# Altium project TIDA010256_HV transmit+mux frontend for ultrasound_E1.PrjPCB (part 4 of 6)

## Sheet 17_AM243x_SocPower.SchDoc
size 431 x 279 mm; Date: Not shown in title block; ApprovedBy: Not shown in title block; CheckedBy: Not shown in title block; Author: Not shown in title block; CompanyName: Not shown in title block; Engineer: Not shown in title block; Organization: Not shown in title block; Address1: Not shown in title block; Address2: Not shown in title block; Address3: Not shown in title block; Address4: Not shown in title block; DocumentNumber: 9; Revision: Use project parameter SCH_Rev; SheetNumber: 9; SheetTotal: 18; PageSetup: Record=PageOptions¦CenterHorizontal=True¦CenterVertical=True¦PrintScale=1.00¦XCorrection=1.00¦YCorrection=1.00¦PrintKind=0¦BorderSize=5000000¦LeftOffset=0¦BottomOffset=0¦Orientation=2¦PaperLength=1000¦PaperWidth=1000¦Scale=100¦PaperSource=15¦PrintQuality=600¦MediaType=1¦DitherType=10¦PaperKind=Letter¦PrintScaleMode=1
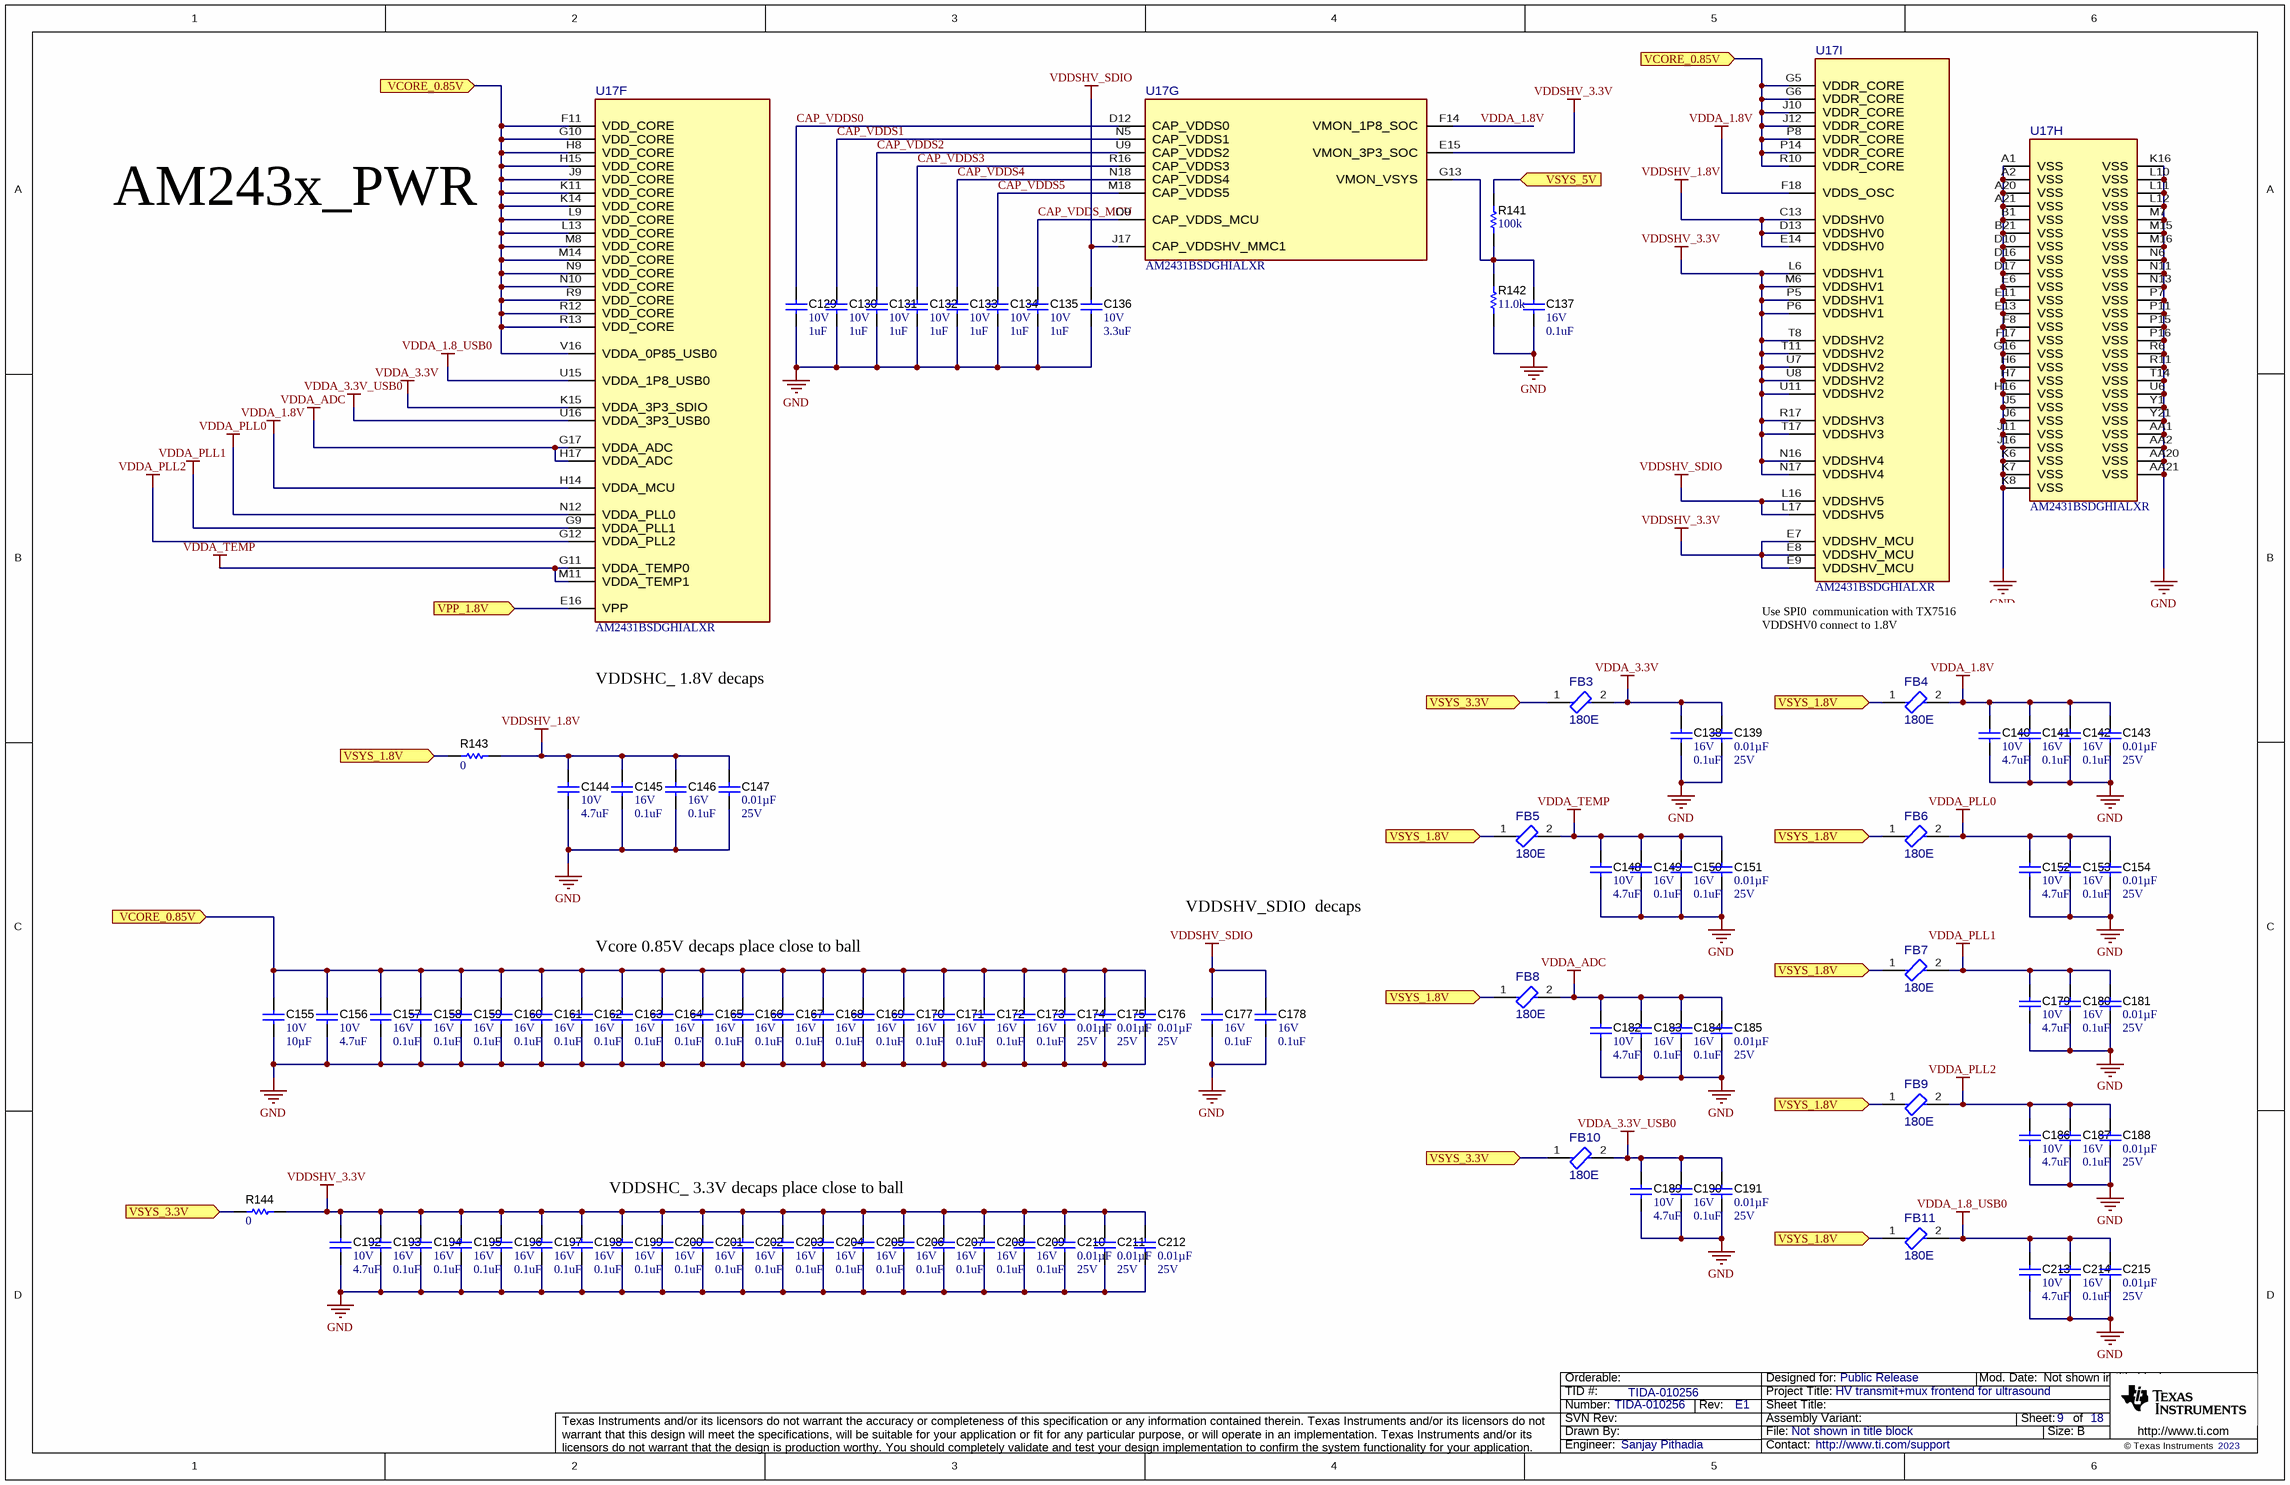
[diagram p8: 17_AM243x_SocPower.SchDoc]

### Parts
C129  VDC_V: 10V  ValueDisplayed: 1uF  [0402]  (hidden comment: GRM155R61A105KE15D)
C130  VDC_V: 10V  ValueDisplayed: 1uF  [0402]  (hidden comment: GRM155R61A105KE15D)
C131  VDC_V: 10V  ValueDisplayed: 1uF  [0402]  (hidden comment: GRM155R61A105KE15D)
C132  VDC_V: 10V  ValueDisplayed: 1uF  [0402]  (hidden comment: GRM155R61A105KE15D)
C133  VDC_V: 10V  ValueDisplayed: 1uF  [0402]  (hidden comment: GRM155R61A105KE15D)
C134  VDC_V: 10V  ValueDisplayed: 1uF  [0402]  (hidden comment: GRM155R61A105KE15D)
C135  VDC_V: 10V  ValueDisplayed: 1uF  [0402]  (hidden comment: GRM155R61A105KE15D)
C136  VDC_V: 10V  ValueDisplayed: 3.3uF  [0603]  (hidden comment: C1608X7S1A335K080AC)
C137  VDC_V: 16V  ValueDisplayed: 0.1uF  [0201_033]  (hidden comment: GRM033R61C104KE84D)
C138  VDC_V: 16V  ValueDisplayed: 0.1uF  [0201_033]  (hidden comment: GRM033R61C104KE84D)
C139  ValueDisplayed: 0.01µF  VDC_V: 25V  [0201]  (hidden comment: GRM033R71E103KE14D)
C140  VDC_V: 10V  ValueDisplayed: 4.7uF  [0402]  (hidden comment: GRM155R61A475MEAAD)
C141  VDC_V: 16V  ValueDisplayed: 0.1uF  [0201_033]  (hidden comment: GRM033R61C104KE84D)
C142  VDC_V: 16V  ValueDisplayed: 0.1uF  [0201_033]  (hidden comment: GRM033R61C104KE84D)
C143  ValueDisplayed: 0.01µF  VDC_V: 25V  [0201]  (hidden comment: GRM033R71E103KE14D)
C144  VDC_V: 10V  ValueDisplayed: 4.7uF  [0402]  (hidden comment: GRM155R61A475MEAAD)
C145  VDC_V: 16V  ValueDisplayed: 0.1uF  [0201_033]  (hidden comment: GRM033R61C104KE84D)
C146  VDC_V: 16V  ValueDisplayed: 0.1uF  [0201_033]  (hidden comment: GRM033R61C104KE84D)
C147  ValueDisplayed: 0.01µF  VDC_V: 25V  [0201]  (hidden comment: GRM033R71E103KE14D)
C148  VDC_V: 10V  ValueDisplayed: 4.7uF  [0402]  (hidden comment: GRM155R61A475MEAAD)
C149  VDC_V: 16V  ValueDisplayed: 0.1uF  [0201_033]  (hidden comment: GRM033R61C104KE84D)
C150  VDC_V: 16V  ValueDisplayed: 0.1uF  [0201_033]  (hidden comment: GRM033R61C104KE84D)
C151  ValueDisplayed: 0.01µF  VDC_V: 25V  [0201]  (hidden comment: GRM033R71E103KE14D)
C152  VDC_V: 10V  ValueDisplayed: 4.7uF  [0402]  (hidden comment: GRM155R61A475MEAAD)
C153  VDC_V: 16V  ValueDisplayed: 0.1uF  [0201_033]  (hidden comment: GRM033R61C104KE84D)
C154  ValueDisplayed: 0.01µF  VDC_V: 25V  [0201]  (hidden comment: GRM033R71E103KE14D)
C155  VDC_V: 10V  ValueDisplayed: 10µF  [0402_070]  (hidden comment: GRM155R61A106ME44)
C156  VDC_V: 10V  ValueDisplayed: 4.7uF  [0402]  (hidden comment: GRM155R61A475MEAAD)
C157  VDC_V: 16V  ValueDisplayed: 0.1uF  [0201_033]  (hidden comment: GRM033R61C104KE84D)
C158  VDC_V: 16V  ValueDisplayed: 0.1uF  [0201_033]  (hidden comment: GRM033R61C104KE84D)
C159  VDC_V: 16V  ValueDisplayed: 0.1uF  [0201_033]  (hidden comment: GRM033R61C104KE84D)
C160  VDC_V: 16V  ValueDisplayed: 0.1uF  [0201_033]  (hidden comment: GRM033R61C104KE84D)
C161  VDC_V: 16V  ValueDisplayed: 0.1uF  [0201_033]  (hidden comment: GRM033R61C104KE84D)
C162  VDC_V: 16V  ValueDisplayed: 0.1uF  [0201_033]  (hidden comment: GRM033R61C104KE84D)
C163  VDC_V: 16V  ValueDisplayed: 0.1uF  [0201_033]  (hidden comment: GRM033R61C104KE84D)
C164  VDC_V: 16V  ValueDisplayed: 0.1uF  [0201_033]  (hidden comment: GRM033R61C104KE84D)
C165  VDC_V: 16V  ValueDisplayed: 0.1uF  [0201_033]  (hidden comment: GRM033R61C104KE84D)
C166  VDC_V: 16V  ValueDisplayed: 0.1uF  [0201_033]  (hidden comment: GRM033R61C104KE84D)
C167  VDC_V: 16V  ValueDisplayed: 0.1uF  [0201_033]  (hidden comment: GRM033R61C104KE84D)
C168  VDC_V: 16V  ValueDisplayed: 0.1uF  [0201_033]  (hidden comment: GRM033R61C104KE84D)
C169  VDC_V: 16V  ValueDisplayed: 0.1uF  [0201_033]  (hidden comment: GRM033R61C104KE84D)
C170  VDC_V: 16V  ValueDisplayed: 0.1uF  [0201_033]  (hidden comment: GRM033R61C104KE84D)
C171  VDC_V: 16V  ValueDisplayed: 0.1uF  [0201_033]  (hidden comment: GRM033R61C104KE84D)
C172  VDC_V: 16V  ValueDisplayed: 0.1uF  [0201_033]  (hidden comment: GRM033R61C104KE84D)
C173  VDC_V: 16V  ValueDisplayed: 0.1uF  [0201_033]  (hidden comment: GRM033R61C104KE84D)
C174  ValueDisplayed: 0.01µF  VDC_V: 25V  [0201]  (hidden comment: GRM033R71E103KE14D)
C175  ValueDisplayed: 0.01µF  VDC_V: 25V  [0201]  (hidden comment: GRM033R71E103KE14D)
C176  ValueDisplayed: 0.01µF  VDC_V: 25V  [0201]  (hidden comment: GRM033R71E103KE14D)
C177  VDC_V: 16V  ValueDisplayed: 0.1uF  [0201_033]  (hidden comment: GRM033R61C104KE84D)
C178  VDC_V: 16V  ValueDisplayed: 0.1uF  [0201_033]  (hidden comment: GRM033R61C104KE84D)
C179  VDC_V: 10V  ValueDisplayed: 4.7uF  [0402]  (hidden comment: GRM155R61A475MEAAD)
C180  VDC_V: 16V  ValueDisplayed: 0.1uF  [0201_033]  (hidden comment: GRM033R61C104KE84D)
C181  ValueDisplayed: 0.01µF  VDC_V: 25V  [0201]  (hidden comment: GRM033R71E103KE14D)
C182  VDC_V: 10V  ValueDisplayed: 4.7uF  [0402]  (hidden comment: GRM155R61A475MEAAD)
C183  VDC_V: 16V  ValueDisplayed: 0.1uF  [0201_033]  (hidden comment: GRM033R61C104KE84D)
C184  VDC_V: 16V  ValueDisplayed: 0.1uF  [0201_033]  (hidden comment: GRM033R61C104KE84D)
C185  ValueDisplayed: 0.01µF  VDC_V: 25V  [0201]  (hidden comment: GRM033R71E103KE14D)
C186  VDC_V: 10V  ValueDisplayed: 4.7uF  [0402]  (hidden comment: GRM155R61A475MEAAD)
C187  VDC_V: 16V  ValueDisplayed: 0.1uF  [0201_033]  (hidden comment: GRM033R61C104KE84D)
C188  ValueDisplayed: 0.01µF  VDC_V: 25V  [0201]  (hidden comment: GRM033R71E103KE14D)
C189  VDC_V: 10V  ValueDisplayed: 4.7uF  [0402]  (hidden comment: GRM155R61A475MEAAD)
C190  VDC_V: 16V  ValueDisplayed: 0.1uF  [0201_033]  (hidden comment: GRM033R61C104KE84D)
C191  ValueDisplayed: 0.01µF  VDC_V: 25V  [0201]  (hidden comment: GRM033R71E103KE14D)
C192  VDC_V: 10V  ValueDisplayed: 4.7uF  [0402]  (hidden comment: GRM155R61A475MEAAD)
C193  VDC_V: 16V  ValueDisplayed: 0.1uF  [0201_033]  (hidden comment: GRM033R61C104KE84D)
C194  VDC_V: 16V  ValueDisplayed: 0.1uF  [0201_033]  (hidden comment: GRM033R61C104KE84D)
C195  VDC_V: 16V  ValueDisplayed: 0.1uF  [0201_033]  (hidden comment: GRM033R61C104KE84D)
C196  VDC_V: 16V  ValueDisplayed: 0.1uF  [0201_033]  (hidden comment: GRM033R61C104KE84D)
C197  VDC_V: 16V  ValueDisplayed: 0.1uF  [0201_033]  (hidden comment: GRM033R61C104KE84D)
C198  VDC_V: 16V  ValueDisplayed: 0.1uF  [0201_033]  (hidden comment: GRM033R61C104KE84D)
C199  VDC_V: 16V  ValueDisplayed: 0.1uF  [0201_033]  (hidden comment: GRM033R61C104KE84D)
C200  VDC_V: 16V  ValueDisplayed: 0.1uF  [0201_033]  (hidden comment: GRM033R61C104KE84D)
C201  VDC_V: 16V  ValueDisplayed: 0.1uF  [0201_033]  (hidden comment: GRM033R61C104KE84D)
C202  VDC_V: 16V  ValueDisplayed: 0.1uF  [0201_033]  (hidden comment: GRM033R61C104KE84D)
C203  VDC_V: 16V  ValueDisplayed: 0.1uF  [0201_033]  (hidden comment: GRM033R61C104KE84D)
C204  VDC_V: 16V  ValueDisplayed: 0.1uF  [0201_033]  (hidden comment: GRM033R61C104KE84D)
C205  VDC_V: 16V  ValueDisplayed: 0.1uF  [0201_033]  (hidden comment: GRM033R61C104KE84D)
C206  VDC_V: 16V  ValueDisplayed: 0.1uF  [0201_033]  (hidden comment: GRM033R61C104KE84D)
C207  VDC_V: 16V  ValueDisplayed: 0.1uF  [0201_033]  (hidden comment: GRM033R61C104KE84D)
C208  VDC_V: 16V  ValueDisplayed: 0.1uF  [0201_033]  (hidden comment: GRM033R61C104KE84D)
C209  VDC_V: 16V  ValueDisplayed: 0.1uF  [0201_033]  (hidden comment: GRM033R61C104KE84D)
C210  ValueDisplayed: 0.01µF  VDC_V: 25V  [0201]  (hidden comment: GRM033R71E103KE14D)
C211  ValueDisplayed: 0.01µF  VDC_V: 25V  [0201]  (hidden comment: GRM033R71E103KE14D)
C212  ValueDisplayed: 0.01µF  VDC_V: 25V  [0201]  (hidden comment: GRM033R71E103KE14D)
C213  VDC_V: 10V  ValueDisplayed: 4.7uF  [0402]  (hidden comment: GRM155R61A475MEAAD)
C214  VDC_V: 16V  ValueDisplayed: 0.1uF  [0201_033]  (hidden comment: GRM033R61C104KE84D)
C215  ValueDisplayed: 0.01µF  VDC_V: 25V  [0201]  (hidden comment: GRM033R71E103KE14D)
FB3  180E  [FP-MPZ1608S181ATAH0_0603-MFG]
FB4  180E  [FP-MPZ1608S181ATAH0_0603-MFG]
FB5  180E  [FP-MPZ1608S181ATAH0_0603-MFG]
FB6  180E  [FP-MPZ1608S181ATAH0_0603-MFG]
FB7  180E  [FP-MPZ1608S181ATAH0_0603-MFG]
FB8  180E  [FP-MPZ1608S181ATAH0_0603-MFG]
FB9  180E  [FP-MPZ1608S181ATAH0_0603-MFG]
FB10  180E  [FP-MPZ1608S181ATAH0_0603-MFG]
FB11  180E  [FP-MPZ1608S181ATAH0_0603-MFG]
R141  ValueDisplayed: 100k  [0402]  (hidden comment: RC0402FR-07100KL)
R142  ValueDisplayed: 11.0k  [0402]  (hidden comment: CRCW040211K0FKED)
R143  ValueDisplayed: 0  [0402]  (hidden comment: RK73Z1ETTP)
R144  ValueDisplayed: 0  [0402]  (hidden comment: RK73Z1ETTP)
U17  AM2431BSDGHIALXR  [ALX0293A-MFG]  (parts F,G,H,I of 9)

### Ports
VCORE_0.85V (in), VPP_1.8V (in), VSYS_1.8V (in), VSYS_3.3V (in), VSYS_5V (in)

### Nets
GND: C129.2 C130.2 C131.2 C132.2 C133.2 C134.2 C135.2 C136.1 C137.2 C138.2 C139.2 C140.2 C141.2 C142.2 C143.2 C144.2 C145.2 C146.2 C147.2 C148.2 C149.2 C150.2 C151.2 C152.2 C153.2 C154.2 C155.2 C156.2 C157.2 C158.2 C159.2 C160.2 C161.2 C162.2 C163.2 C164.2 C165.2 C166.2 C167.2 C168.2 C169.2 C170.2 C171.2 C172.2 C173.2 C174.2 C175.2 C176.2 C177.2 C178.2 C179.2 C180.2 C181.2 C182.2 C183.2 C184.2 C185.2 C186.2 C187.2 C188.2 C189.2 C190.2 C191.2 C192.2 C193.2 C194.2 C195.2 C196.2 C197.2 C198.2 C199.2 C200.2 C201.2 C202.2 C203.2 C204.2 C205.2 C206.2 C207.2 C208.2 C209.2 C210.2 C211.2 C212.2 C213.2 C214.2 C215.2 R142.1 U17.A1(VSS) U17.A2(VSS) U17.A20(VSS) U17.A21(VSS) U17.AA1(VSS) U17.AA2(VSS) U17.AA20(VSS) U17.AA21(VSS) U17.B1(VSS) U17.B21(VSS) U17.D10(VSS) U17.D16(VSS) U17.D17(VSS) U17.E6(VSS) U17.E11(VSS) U17.E13(VSS) U17.F8(VSS) U17.F17(VSS) U17.G16(VSS) U17.H6(VSS) U17.H7(VSS) U17.H16(VSS) U17.J5(VSS) U17.J6(VSS) U17.J11(VSS) U17.J16(VSS) U17.K6(VSS) U17.K7(VSS) U17.K8(VSS) U17.K16(VSS) U17.L10(VSS) U17.L11(VSS) U17.L12(VSS) U17.M7(VSS) U17.M15(VSS) U17.M16(VSS) U17.N6(VSS) U17.N11(VSS) U17.N13(VSS) U17.P7(VSS) U17.P11(VSS) U17.P15(VSS) U17.P16(VSS) U17.R6(VSS) U17.R11(VSS) U17.T14(VSS) U17.U6(VSS) U17.Y1(VSS) U17.Y21(VSS)
VDDA_1.8_USB0: C213.1 C214.1 C215.1 FB11.2 U17.U15(VDDA_1P8_USB0)
VDDA_1.8V: C140.1 C141.1 C142.1 C143.1 FB4.2 U17.F14(VMON_1P8_SOC) U17.F18(VDDS_OSC) U17.H14(VDDA_MCU)
VDDA_3.3V: C138.1 C139.1 FB3.2 U17.K15(VDDA_3P3_SDIO)
VDDA_3.3V_USB0: C189.1 C190.1 C191.1 FB10.2 U17.U16(VDDA_3P3_USB0)
VDDA_ADC: C182.1 C183.1 C184.1 C185.1 FB8.2 U17.G17(VDDA_ADC) U17.H17(VDDA_ADC)
VDDA_PLL0: C152.1 C153.1 C154.1 FB6.2 U17.N12(VDDA_PLL0)
VDDA_PLL1: C179.1 C180.1 C181.1 FB7.2 U17.G9(VDDA_PLL1)
VDDA_PLL2: C186.1 C187.1 C188.1 FB9.2 U17.G12(VDDA_PLL2)
VDDA_TEMP: C148.1 C149.1 C150.1 C151.1 FB5.2 U17.G11(VDDA_TEMP0) U17.M11(VDDA_TEMP1)
VDDSHV_1.8V: C144.1 C145.1 C146.1 C147.1 R143.2 U17.C13(VDDSHV0) U17.D13(VDDSHV0) U17.E14(VDDSHV0)
VDDSHV_3.3V: C192.1 C193.1 C194.1 C195.1 C196.1 C197.1 C198.1 C199.1 C200.1 C201.1 C202.1 C203.1 C204.1 C205.1 C206.1 C207.1 C208.1 C209.1 C210.1 C211.1 C212.1 R144.2 U17.E7(VDDSHV_MCU) U17.E8(VDDSHV_MCU) U17.E9(VDDSHV_MCU) U17.E15(VMON_3P3_SOC) U17.L6(VDDSHV1) U17.M6(VDDSHV1) U17.N16(VDDSHV4) U17.N17(VDDSHV4) U17.P5(VDDSHV1) U17.P6(VDDSHV1) U17.R17(VDDSHV3) U17.T8(VDDSHV2) U17.T11(VDDSHV2) U17.T17(VDDSHV3) U17.U7(VDDSHV2) U17.U8(VDDSHV2) U17.U11(VDDSHV2)
VDDSHV_SDIO: C136.2 C177.1 C178.1 U17.J17(CAP_VDDSHV_MMC1) U17.L16(VDDSHV5) U17.L17(VDDSHV5)
CAP_VDDS0: C129.1 U17.D12(CAP_VDDS0)
CAP_VDDS1: C130.1 U17.N5(CAP_VDDS1)
CAP_VDDS2: C131.1 U17.U9(CAP_VDDS2)
CAP_VDDS3: C132.1 U17.R16(CAP_VDDS3)
CAP_VDDS4: C133.1 U17.N18(CAP_VDDS4)
CAP_VDDS5: C134.1 U17.M18(CAP_VDDS5)
CAP_VDDS_MCU: C135.1 U17.D9(CAP_VDDS_MCU)
VCORE_0.85V: C155.1 C156.1 C157.1 C158.1 C159.1 C160.1 C161.1 C162.1 C163.1 C164.1 C165.1 C166.1 C167.1 C168.1 C169.1 C170.1 C171.1 C172.1 C173.1 C174.1 C175.1 C176.1 U17.F11(VDD_CORE) U17.G5(VDDR_CORE) U17.G6(VDDR_CORE) U17.G10(VDD_CORE) U17.H8(VDD_CORE) U17.H15(VDD_CORE) U17.J9(VDD_CORE) U17.J10(VDDR_CORE) U17.J12(VDDR_CORE) U17.K11(VDD_CORE) U17.K14(VDD_CORE) U17.L9(VDD_CORE) U17.L13(VDD_CORE) U17.M8(VDD_CORE) U17.M14(VDD_CORE) U17.N9(VDD_CORE) U17.N10(VDD_CORE) U17.P8(VDDR_CORE) U17.P14(VDDR_CORE) U17.R9(VDD_CORE) U17.R10(VDDR_CORE) U17.R12(VDD_CORE) U17.R13(VDD_CORE) U17.V16(VDDA_0P85_USB0) ; port VCORE_0.85V
VSYS_1.8V: FB4.1 FB5.1 FB6.1 FB7.1 FB8.1 FB9.1 FB11.1 R143.1 ; port VSYS_1.8V
VSYS_3.3V: FB3.1 FB10.1 R144.1 ; port VSYS_3.3V
VSYS_5V: R141.2 ; port VSYS_5V
NetC96_1: U17.E16(VPP) ; port VPP_1.8V
NetC137_1: C137.1 R141.1 R142.2 U17.G13(VMON_VSYS)

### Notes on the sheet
- AM243x_PWR
- (near U17) Use SPI0  communication with TX7516
  VDDSHV0 connect to 1.8V
- VDDSHC_ 1.8V decaps
- Vcore 0.85V decaps place close to ball
- VDDSHV_SDIO  decaps
- VDDSHC_ 3.3V decaps place close to ball

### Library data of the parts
C129-C135 = CMP-0006563-2: CAP, CERM, 1 uF, 10 V, +/- 10%, X5R, 0402; Manufacturer: MuRata; TaMin_C: -55°C; Polarized: N; SizeAreaWB_mm2: 3; Value1: Unknown; U/M: EA; Value: 1uF; TaMax_C: 85°C; SizeZ_mm: 0.6; SizeX_mm: 1; SizeY_mm: 0.5; Cap_F: 1µF; AEC Category: Q200
C136 = CMP-0007057-4: CAP, CERM, 3.3 uF, 10 V, +/- 10%, X7S, 0603; Manufacturer: TDK; TaMin_C: -55°C; ESR_ohm: 4.796m; Polarized: N; SizeAreaWB_mm2: 4.68; Value1: 0.004796 ohm; U/M: EA; Value: 3.3uF; TaMax_C: 125°C; SizeZ_mm: 1; SizeX_mm: 1.6; SizeY_mm: 0.8; SizeArea_mm2: 1.28; Cap_F: 3.3µF; IRMS_A: 2.37519A; AEC Category: Q200
C137 C138 C141 C142 C145 C146 C149 C150 C153 C157-C173 C177 C178 C180 C183 C184 C187 C190 C193-C209 C214 = CMP-0009717-2: CAP, CERM, 0.1 uF, 16 V, +/- 10%, X5R, 0201; Manufacturer: MuRata; TaMin_C: -55°C; Polarized: N; SizeAreaWB_mm2: 2.08; Value1: Unknown; U/M: EA; Value: 0.1uF; TaMax_C: 85°C; SizeZ_mm: 0.33; SizeX_mm: 0.6; SizeY_mm: 0.3; Cap_Case: 0201; SizeArea_mm2: 0.18; Cap_F: 100nF; AEC Category: Q200
C139 C143 C147 C151 C154 C174-C176 C181 C185 C188 C191 C210-C212 C215 = CMP-0860568-1: CAP, CERM, 0.01 µF, 25 V,+/- 10%, X7R, 0201; Manufacturer: MuRata; U/M: EA; TaMax_C: 125°C; SizeZ_mm: 0.26; AEC Qualified: N; TaMin_C: -55°C; SizeY_mm: 0.3; AEC Category: Q200; SizeAreaWB_mm2: 2.08; Cap_F: 10nF; SizeX_mm: 0.6; Value: 0.01uF; SizeArea_mm2: 0.18
C140 C144 C148 C152 C156 C179 C182 C186 C189 C192 C213 = CMP-0006582-2: CAP, CERM, 4.7 uF, 10 V, +/- 20%, X5R, 0402; Manufacturer: MuRata; TaMin_C: -55°C; Polarized: N; SizeAreaWB_mm2: 3; Value1: Unknown; U/M: EA; Value: 4.7uF; TaMax_C: 85°C; SizeZ_mm: 0.6; SizeX_mm: 1; SizeY_mm: 0.5; Cap_F: 4.7µF; AEC Category: Q200
C155 = CMP-0074692-1: CAP, CERM, 10 µF, 10 V,+/- 20%, X5R, 0402; Manufacturer: MuRata; TaMin_C: -55°C; Polarized: N; Green_Lifecycle: Not Set; SizeAreaWB_mm2: 3.0; Green_REACh: Incomplete; U/M: EA; Value: 10uF; TaMax_C: 85°C; SizeZ_mm: 0.7; SizeX_mm: 1.0; SizeY_mm: 0.5; Cap_Case: 0402; AEC Category: Q200
FB3-FB11 = CMP-0092257-1: 180 Ohms @ 100MHz 1 Power Line Ferrite Bead 0603 (1608 Metric) 2A 50mOhm; PartNumber: MPZ1608S181ATAH0; Manufacturer: TDK Corporation; SizeZ_mm: 0.75mm; Tolerance_%: 25%; AEC Qualified: No; Impedance At Frequency: 180Ω @ 100MHz; DCR_ohm: 50m
R141 = CMP-0026721-1: RES, 100 k, 1%, 0.0625 W, 0402; Manufacturer: Yageo America; Power_W: 62.5mW; TempCo: 100 ppm/C; U/M: EA; Value: 100k; EIA_Code: E96; SizeX_mm: 1; SizeY_mm: 0.5; SizeZ_mm: 0.6; AEC Qualified: N; VDC_V: 50V; AEC Category: Q200
R142 = CMP-0025975-3: RES, 11.0 k, 1%, 0.063 W, AEC-Q200 Grade 0, 0402; Manufacturer: Vishay-Dale; Power_W: 63mW; TempCo: 100 ppm/C; Value_Code: 11k0; Value: 11.0k; EIA_Code: E96; Res_ohm: 11k; SizeX_mm: 1; SizeY_mm: 0.5; SizeZ_mm: 0.6; Value2: 0.063W; AEC Qualified: Y; VDC_V: 50V; AEC Category: Q200; AEC Grade: 0
R143 R144 = CMP-0027007-2: RES, 0, 5%, 0.063 W, AEC-Q200 Grade 0, 0402; Manufacturer: KOA Speer; Power_W: 63mW; TempCo: ppm/C; Value_Code: 0000; U/M: EA; Value: 0; EIA_Code: E24; SizeX_mm: 1; SizeY_mm: 0.5; SizeZ_mm: 0.6; Value2: 0.063W; AEC Qualified: Y; AEC Category: Q200
U17 = CMP-0035022-1: Arm® Cortex®-R5F-based MCU with industrial communications and security up to 800 MHz 293-FCCSP -40 to 125; Manufacturer: Texas Instruments; Number Of Pwm Channels: 7; Number Of Usb Channels: 1; Number Of Cores: 2; Standoff Height: 0.15mm; Ram Size: 2MBytes; Number Of I2C Channels: 3; Number Of Spi Channels: 4; SizeZ_mm: 1mm; Frequency_Fixed: 800MHz; Number Of I/Os: 148; AEC Qualified: No; Data Bus Width: 32bits; Core Architecture: Arm Cortex-R5F, Arm Cortex-M4F; TJmax_C: +125°C; Number Of Timers/Counters: 16; Max Supply Voltage: 3.465V; Min Supply Voltage: 810mV; Interface: I2C,SPI,UART,CAN,USB,Ethernet,PCIe,Other; Number Of Adc Channels: 8; Memory Type: OTHER

## Sheet 18_AM243x_Pinout.SchDoc
size 431 x 279 mm; Date: Not shown in title block; ApprovedBy: Not shown in title block; CheckedBy: Not shown in title block; Author: Not shown in title block; CompanyName: Not shown in title block; Engineer: Not shown in title block; Organization: Not shown in title block; Address1: Not shown in title block; Address2: Not shown in title block; Address3: Not shown in title block; Address4: Not shown in title block; DocumentNumber: 10; Revision: Use project parameter SCH_Rev; SheetNumber: 10; SheetTotal: 18; PageSetup: Record=PageOptions¦CenterHorizontal=True¦CenterVertical=True¦PrintScale=1.00¦XCorrection=1.00¦YCorrection=1.00¦PrintKind=0¦BorderSize=5000000¦LeftOffset=0¦BottomOffset=0¦Orientation=2¦PaperLength=1000¦PaperWidth=1000¦Scale=100¦PaperSource=15¦PrintQuality=600¦MediaType=1¦DitherType=10¦PaperKind=Letter¦PrintScaleMode=1
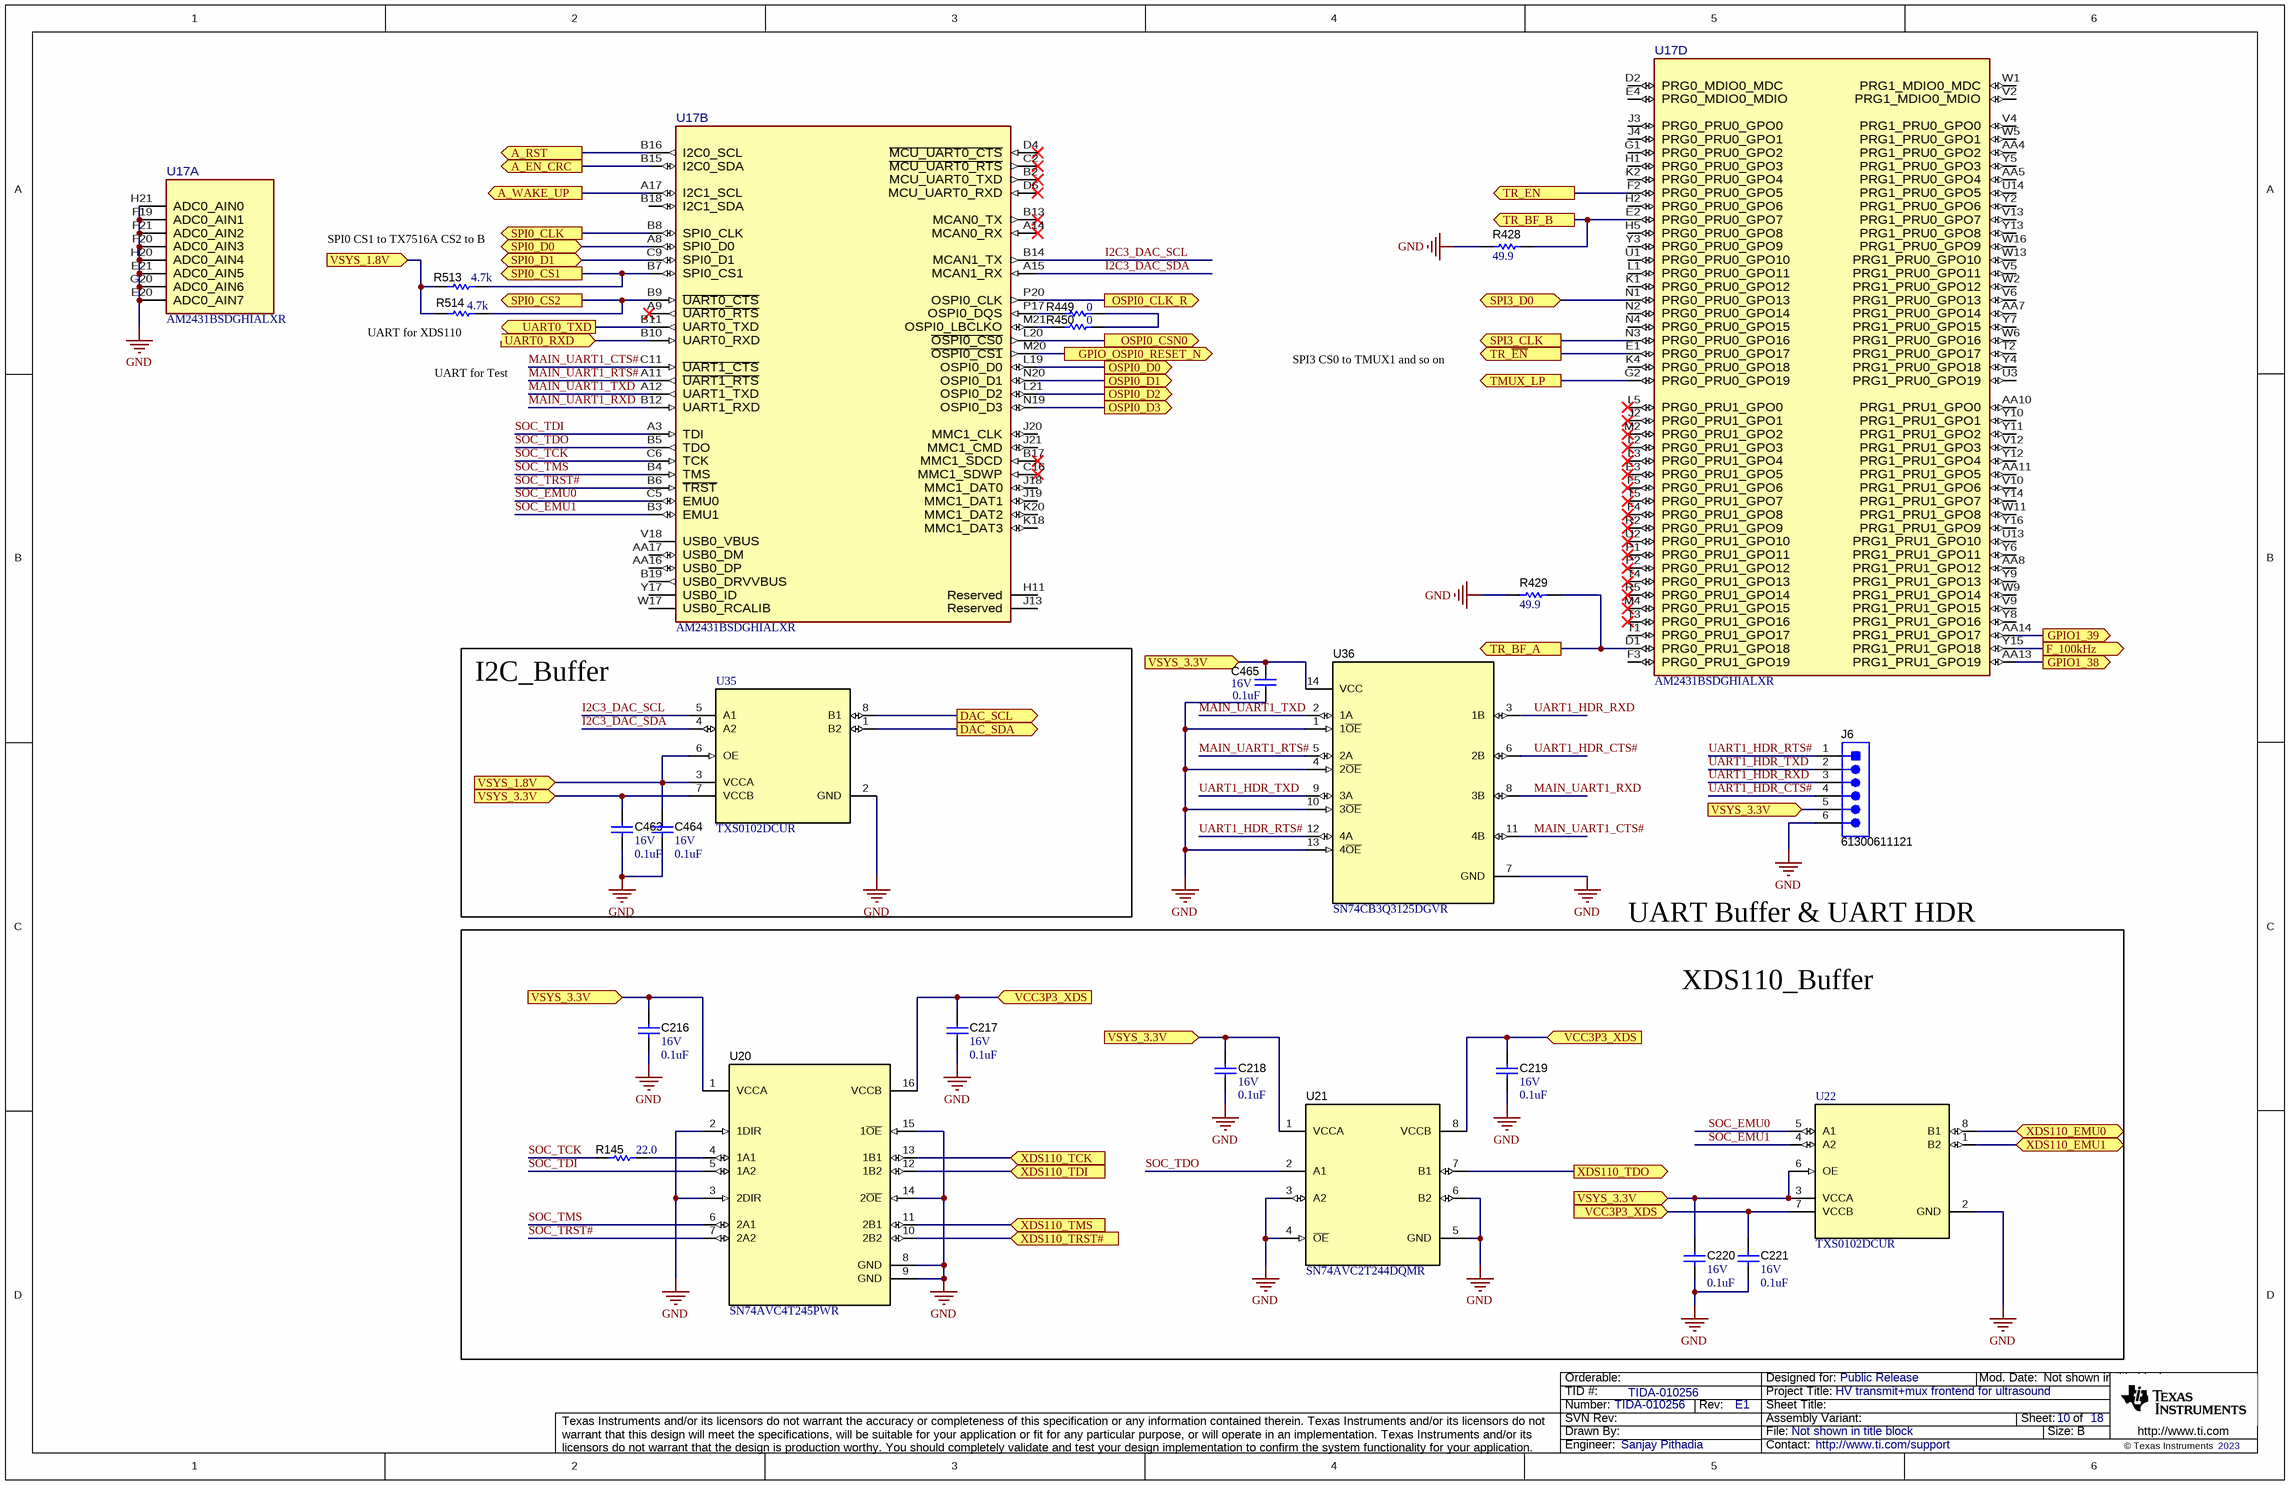
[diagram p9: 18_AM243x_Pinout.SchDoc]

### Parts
C216  VDC_V: 16V  ValueDisplayed: 0.1uF  [0201_033]  (hidden comment: GRM033R61C104KE84D)
C217  VDC_V: 16V  ValueDisplayed: 0.1uF  [0201_033]  (hidden comment: GRM033R61C104KE84D)
C218  VDC_V: 16V  ValueDisplayed: 0.1uF  [0201_033]  (hidden comment: GRM033R61C104KE84D)
C219  VDC_V: 16V  ValueDisplayed: 0.1uF  [0201_033]  (hidden comment: GRM033R61C104KE84D)
C220  VDC_V: 16V  ValueDisplayed: 0.1uF  [0201_033]  (hidden comment: GRM033R61C104KE84D)
C221  VDC_V: 16V  ValueDisplayed: 0.1uF  [0201_033]  (hidden comment: GRM033R61C104KE84D)
C463  VDC_V: 16V  ValueDisplayed: 0.1uF  [0201_033]  (hidden comment: GRM033R61C104KE84D)
C464  VDC_V: 16V  ValueDisplayed: 0.1uF  [0201_033]  (hidden comment: GRM033R61C104KE84D)
C465  VDC_V: 16V  ValueDisplayed: 0.1uF  [0201_033]  (hidden comment: GRM033R61C104KE84D)
J6  61300611121  [WURTH_61300611121]
R145  ValueDisplayed: 22.0  [0201]  (hidden comment: RC0201FR-0722RL)
R428  ValueDisplayed: 49.9  [0402]  (hidden comment: RMCF0402FT49R9)
R429  ValueDisplayed: 49.9  [0402]  (hidden comment: RMCF0402FT49R9)
R449  ValueDisplayed: 0  [0402]  (hidden comment: RC0402JR-070RL)
R450  ValueDisplayed: 0  [0402]  (hidden comment: RC0402JR-070RL)
R513  ValueDisplayed: 4.7k  [0603]  (hidden comment: CRCW06034K70JNEA)
R514  ValueDisplayed: 4.7k  [0603]  (hidden comment: CRCW06034K70JNEA)
U17  AM2431BSDGHIALXR  [ALX0293A-MFG]  (parts A,B,D of 9)
U20  SN74AVC4T245PWR  [PW0016A_N]
U21  SN74AVC2T244DQMR  [DQM0008A]
U22  TXS0102DCUR  [DCU0008A_N]
U35  TXS0102DCUR  [DCU0008A_N]
U36  SN74CB3Q3125DGVR  [DGV0014A_N]

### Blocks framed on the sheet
I2C_Buffer: C463 C464 U35

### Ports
A_EN_CRC (out), A_RST (out), A_WAKE_UP (out), DAC_SCL (out), DAC_SDA (out), F_100kHz (out), GPIO1_38 (out), GPIO1_39 (out), GPIO_OSPI0_RESET_N (out), OSPI0_CLK_R (out), OSPI0_CSN0 (out), OSPI0_D0 (out), OSPI0_D1 (out), OSPI0_D2 (out), OSPI0_D3 (out), SPI0_CLK (out), SPI0_CS1 (out), SPI0_CS2 (out), SPI0_D0 (bidir), SPI0_D1 (bidir), SPI3_CLK (out), SPI3_D0 (bidir), TMUX_LP (out), TR_BF_A (out), TR_BF_B (out), TR_EN (out), TR_~{EN} (out), UART0_RXD (in), UART0_TXD (out), VCC3P3_XDS (in), VSYS_1.8V (in), VSYS_3.3V (in), XDS110_EMU0 (bidir), XDS110_EMU1 (bidir), XDS110_TCK (in), XDS110_TDI (in), XDS110_TDO (out), XDS110_TMS (in), XDS110_TRST# (in)

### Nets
GND: C216.2 C217.2 C218.2 C219.2 C220.2 C221.2 C463.2 C464.2 C465.2 J6.6 R428.1 R429.1 U17.E20(ADC0_AIN7) U17.E21(ADC0_AIN5) U17.F19(ADC0_AIN1) U17.F20(ADC0_AIN3) U17.F21(ADC0_AIN2) U17.G20(ADC0_AIN6) U17.H20(ADC0_AIN4) U17.H21(ADC0_AIN0) U20.2(1DIR) U20.3(2DIR) U20.8(GND) U20.9(GND) U20.14(2~{OE}) U20.15(1~{OE}) U21.3(A2) U21.4(~{OE}) U21.5(GND) U21.6(B2) U22.2(GND) U35.2(GND) U36.1(1~{OE}) U36.4(2~{OE}) U36.7(GND) U36.10(3~{OE}) U36.13(4~{OE})
I2C3_DAC_SCL: U17.B14(MCAN1_TX) U35.5(A1)
I2C3_DAC_SDA: U17.A15(MCAN1_RX) U35.4(A2)
MAIN_UART1_CTS#: U17.C11(~{UART1_CTS}) U36.11(4B)
MAIN_UART1_RTS#: U17.A11(~{UART1_RTS}) U36.5(2A)
MAIN_UART1_RXD: U17.B12(UART1_RXD) U36.8(3B)
MAIN_UART1_TXD: U17.A12(UART1_TXD) U36.2(1A)
SOC_EMU0: U17.C5(EMU0) U22.5(A1)
SOC_EMU1: U17.B3(EMU1) U22.4(A2)
SOC_TCK: R145.1 U17.C6(TCK)
SOC_TDI: U17.A3(TDI) U20.5(1A2)
SOC_TDO: U17.B5(TDO) U21.2(A1)
SOC_TMS: U17.B4(TMS) U20.6(2A1)
SOC_TRST#: U17.B6(~{TRST}) U20.7(2A2)
UART1_HDR_CTS#: J6.4 U36.6(2B)
UART1_HDR_RTS#: J6.1 U36.12(4A)
UART1_HDR_RXD: J6.3 U36.3(1B)
UART1_HDR_TXD: J6.2 U36.9(3A)
VCC3P3_XDS: C217.1 C219.1 C221.1 U20.16(VCCB) U21.8(VCCB) U22.7(VCCB) ; port VCC3P3_XDS
VSYS_1.8V: C464.1 R513.1 R514.1 U35.3(VCCA) U35.6(OE) ; port VSYS_1.8V
VSYS_3.3V: C216.1 C218.1 C220.1 C463.1 C465.1 J6.5 U20.1(VCCA) U21.1(VCCA) U22.3(VCCA) U22.6(OE) U35.7(VCCB) U36.14(VCC) ; port VSYS_3.3V
NetQ2_1: U17.Y15(PRG1_PRU1_GPO18) ; port F_100kHz
NetQ5_3: U17.AA14(PRG1_PRU1_GPO17) ; port GPIO1_39
NetQ6_3: U17.AA13(PRG1_PRU1_GPO19) ; port GPIO1_38
NetR1_1: U35.8(B1) ; port DAC_SCL
NetR2_1: U35.1(B2) ; port DAC_SDA
NetR81_1: U17.B11(UART0_TXD) ; port UART0_TXD
NetR145_2: R145.2 U20.4(1A1)
NetR428_2: R428.2 U17.E2(PRG0_PRU0_GPO7) ; port TR_BF_B
NetR429_2: R429.2 U17.D1(PRG0_PRU1_GPO18) ; port TR_BF_A
NetR438_2: U17.F2(PRG0_PRU0_GPO5) ; port TR_EN
NetR439_2: U17.E1(PRG0_PRU0_GPO17) ; port TR_~{EN}
NetR443_1: U17.P20(OSPI0_CLK) ; port OSPI0_CLK_R
NetR445_1: U17.L20(~{OSPI0_CS0}) ; port OSPI0_CSN0
NetR446_1: U17.M20(~{OSPI0_CS1}) ; port GPIO_OSPI0_RESET_N
NetR449_1: R449.1 U17.P17(OSPI0_DQS)
NetR449_2: R449.2 R450.2
NetR450_1: R450.1 U17.M21(OSPI0_LBCLKO)
NetR488_1: U17.G2(PRG0_PRU0_GPO19) ; port TMUX_LP
NetR513_2: R513.2 U17.B7(SPI0_CS1) ; port SPI0_CS1
NetR514_2: R514.2 U17.B9(~{UART0_CTS}) ; port SPI0_CS2
NetU12_35: U20.13(1B1) ; port XDS110_TCK
NetU12_36: U20.11(2B1) ; port XDS110_TMS
NetU12_37: U21.7(B1) ; port XDS110_TDO
NetU12_38: U20.12(1B2) ; port XDS110_TDI
NetU12_40: U20.10(2B2) ; port XDS110_TRST#
NetU12_42: U22.8(B1) ; port XDS110_EMU0
NetU12_43: U22.1(B2) ; port XDS110_EMU1
NetU15_4: U17.B10(UART0_RXD) ; port UART0_RXD
NetU17_A8: U17.A8(SPI0_D0) ; port SPI0_D0
NetU17_A17: U17.A17(I2C1_SCL) ; port A_WAKE_UP
NetU17_B8: U17.B8(SPI0_CLK) ; port SPI0_CLK
NetU17_B15: U17.B15(I2C0_SDA) ; port A_EN_CRC
NetU17_B16: U17.B16(I2C0_SCL) ; port A_RST
NetU17_C9: U17.C9(SPI0_D1) ; port SPI0_D1
NetU17_L19: U17.L19(OSPI0_D0) ; port OSPI0_D0
NetU17_L21: U17.L21(OSPI0_D2) ; port OSPI0_D2
NetU17_N1: U17.N1(PRG0_PRU0_GPO13) ; port SPI3_D0
NetU17_N3: U17.N3(PRG0_PRU0_GPO16) ; port SPI3_CLK
NetU17_N19: U17.N19(OSPI0_D3) ; port OSPI0_D3
NetU17_N20: U17.N20(OSPI0_D1) ; port OSPI0_D1

Not connected (* = marked no-connect by the designer): U17 A9(~{UART0_RTS})* A14(MCAN0_RX)* AA4(PRG1_PRU0_GPO2) AA5(PRG1_PRU0_GPO4) AA7(PRG1_PRU0_GPO14) AA8(PRG1_PRU1_GPO12) AA10(PRG1_PRU1_GPO0) AA11(PRG1_PRU1_GPO5) AA16(USB0_DP) AA17(USB0_DM) B2(MCU_UART0_TXD)* B13(MCAN0_TX)* B17(MMC1_SDCD)* B18(I2C1_SDA) B19(USB0_DRVVBUS) C2(~{MCU_UART0_RTS})* C16(MMC1_SDWP)* D2(PRG0_MDIO0_MDC) D4(~{MCU_UART0_CTS})* D6(MCU_UART0_RXD)* E3(PRG0_PRU1_GPO5)* E4(PRG0_MDIO0_MDIO) F3(PRG0_PRU1_GPO19) F4(PRG0_PRU1_GPO8)* F5(PRG0_PRU1_GPO6)* G1(PRG0_PRU0_GPO2) H1(PRG0_PRU0_GPO3) H2(PRG0_PRU0_GPO6) H5(PRG0_PRU0_GPO8) H11(Reserved) J2(PRG0_PRU1_GPO1)* J3(PRG0_PRU0_GPO0) J4(PRG0_PRU0_GPO1) J13(Reserved) J18(MMC1_DAT0) J19(MMC1_DAT1) J20(MMC1_CLK) J21(MMC1_CMD) K1(PRG0_PRU0_GPO12) K2(PRG0_PRU0_GPO4) K4(PRG0_PRU0_GPO18) K18(MMC1_DAT3) K20(MMC1_DAT2) L1(PRG0_PRU0_GPO11) L2(PRG0_PRU1_GPO3)* L3(PRG0_PRU1_GPO4)* L5(PRG0_PRU1_GPO0)* M2(PRG0_PRU1_GPO2)* M4(PRG0_PRU1_GPO15)* N2(PRG0_PRU0_GPO14) N4(PRG0_PRU0_GPO15) P1(PRG0_PRU1_GPO11)* P2(PRG0_PRU1_GPO12)* R2(PRG0_PRU1_GPO9)* R5(PRG0_PRU1_GPO14)* T1(PRG0_PRU1_GPO17) T2(PRG1_PRU0_GPO17) T3(PRG0_PRU1_GPO16)* T4(PRG0_PRU1_GPO13)* T5(PRG0_PRU1_GPO7)* U1(PRG0_PRU0_GPO10) U2(PRG0_PRU1_GPO10)* U3(PRG1_PRU0_GPO19) U13(PRG1_PRU1_GPO10) U14(PRG1_PRU0_GPO5) V2(PRG1_MDIO0_MDIO) V4(PRG1_PRU0_GPO0) V5(PRG1_PRU0_GPO11) V6(PRG1_PRU0_GPO13) V9(PRG1_PRU1_GPO15) V10(PRG1_PRU1_GPO6) V12(PRG1_PRU1_GPO3) V13(PRG1_PRU0_GPO7) V18(USB0_VBUS) W1(PRG1_MDIO0_MDC) W2(PRG1_PRU0_GPO12) W5(PRG1_PRU0_GPO1) W6(PRG1_PRU0_GPO16) W9(PRG1_PRU1_GPO14) W11(PRG1_PRU1_GPO8) W13(PRG1_PRU0_GPO10) W16(PRG1_PRU0_GPO9) W17(USB0_RCALIB) Y2(PRG1_PRU0_GPO6) Y3(PRG0_PRU0_GPO9) Y4(PRG1_PRU0_GPO18) Y5(PRG1_PRU0_GPO3) Y6(PRG1_PRU1_GPO11) Y7(PRG1_PRU0_GPO15) Y8(PRG1_PRU1_GPO16) Y9(PRG1_PRU1_GPO13) Y10(PRG1_PRU1_GPO1) Y11(PRG1_PRU1_GPO2) Y12(PRG1_PRU1_GPO4) Y13(PRG1_PRU0_GPO8) Y14(PRG1_PRU1_GPO7) Y16(PRG1_PRU1_GPO9) Y17(USB0_ID)

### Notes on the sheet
- (near R513) SPI0 CS1 to TX7516A CS2 to B
- (near R514) UART for XDS110
- SPI3 CS0 to TMUX1 and so on
- UART for Test
- UART Buffer & UART HDR
- XDS110_Buffer

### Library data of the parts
C216-C221 C463-C465 = CMP-0009717-2: as C137 on sheet 17_AM243x_SocPower
J6 = CMP-0054801-2: Header, 2.54 mm, 6x1, Gold, TH; Manufacturer: Wurth Elektronik; Cert_UL: Y; Gender: Male; Row_Count: 1; Shrouded: N; Pitch_mm: 2.54
R145 = CMP-0027500-1: RES, 22.0, 1%, 0.05 W, 0201; Manufacturer: Yageo America; Power_W: 50mW; TempCo: 200 ppm/C; Value_Code: 22R0; U/M: EA; Value: 22.0; Res_ohm: 22; SizeX_mm: 0.6; SizeY_mm: 0.3; SizeZ_mm: 0.26; Value2: 0.05W; SizeArea_mm2: 0.18; AEC Qualified: N; VDC_V: 25V; AEC Category: Q200
R428 R429 = CMP-0026761-1: RES, 49.9, 1%, 0.063 W, AEC-Q200 Grade 0, 0402; Manufacturer: Stackpole Electronics Inc; Power_W: 63mW; TempCo: 100 ppm/C; Value_Code: 49R9; U/M: EA; Value: 49.9; EIA_Code: E96; SizeX_mm: 1; SizeY_mm: 0.5; SizeZ_mm: 0.6; Value2: 0.063W; AEC Qualified: Y; VDC_V: 50V; AEC Grade: 0; AEC Category: Q200
R449 R450 = CMP-0027004-2: RES, 0, 5%, 0.063 W, 0402; Manufacturer: Yageo America; Power_W: 63mW; TempCo: 200 ppm/C; Value_Code: 0000; U/M: EA; Value: 0; EIA_Code: E24; SizeX_mm: 1; SizeY_mm: 0.5; SizeZ_mm: 0.6; Value2: 0.063W; VDC_V: 50V; AEC Category: Q200
R513 R514 = CMP-0025817-4: RES, 4.7 k, 5%, 0.1 W, AEC-Q200 Grade 0, 0603; Manufacturer: Vishay-Dale; Power_W: 100mW; TempCo: 200 ppm/C; Value_Code: 4k70; Value: 4.7k; EIA_Code: E24; SizeX_mm: 1.6; SizeY_mm: 0.8; SizeZ_mm: 1; Value2: 0.1W; SizeArea_mm2: 1.28; AEC Qualified: Y; VDC_V: 75V; AEC Category: Q200; AEC Grade: 0
U17 = CMP-0035022-1: as U17 on sheet 17_AM243x_SocPower
U20 = CMP-0066448-2: 4-Bit Dual-Supply Bus Transceiver with Configurable Voltage-Level Shifting and 3-State Outputs, PW0016A (TSSOP-16); Alternate Manufacturer: Texas Instruments; Green_Lifecycle: Active; SizeAreaWB_mm2: 58.8; Green_REACh: Passed; SizeZ_mm: 1.2; SizeX_mm: 6.4; SizeY_mm: 5.0; SizeArea_mm2: 32.0; CompType: IC; AEC Category: Q200; AEC Qualified: N
U21 = CMP-0050936-4: Dual-Bit Dual-Supply Bus Transceiver, DQM0008A (X2SON-8); Manufacturer: Texas Instruments; Output Type: CMOS; Bits(#): 2; Technology Family: AVC; Schmitt Trigger: No; VCC(Max)(V): 3.6; Sub-Family: Dual Supply Translator; Rating: Catalog; Output Drive (IOL/IOH)(Max)(mA): 24/-24; ICC @ Nom Voltage(Max)(mA): 0.0009; VCC(Min)(V): 0.9; F @ Nom Voltage(Max)(Mhz): 100; Logic: True; Voltage(Nom)(V): 0.9,1.2,1.5,1.8,2.5,3.3; tpd @ Nom Voltage(Max)(ns): 20,7,3.5; AEC Category: Q200; AEC Qualified: N; CompType: IC; Green_Lifecycle: Active; Green_REACh: Passed; SizeAreaWB_mm2: 6.16; SizeArea_mm2: 2.16; SizeX_mm: 1.2; SizeY_mm: 1.8; SizeZ_mm: 0.4
U22 U35 = CMP-0051209-2: 2-Bit Bidirectional Voltage-Level Shifter for Open-Drain and Push-Pull Application, DCU0008A (VSSOP-8); Manufacturer: Texas Instruments; Propagation Delay: 4.6 ns Max.; Number of Channels: 2; VCCB: 2.3 to 5.5 V; Packing: Tape and Reel; Data Rate: 24 Mbps; VCCA: 1.65 to 3.6 V; AEC Category: Q200; AEC Qualified: N; CompType: IC; Rating: Catalog; SizeAreaWB_mm2: 12.6; SizeArea_mm2: 6.4; SizeX_mm: 3.2; SizeY_mm: 2.0; SizeZ_mm: 0.9
U36 = CMP-0066249-2: Quadruple FET 2.5-V/3.3-V Low-Voltage High-Bandwidth Bus Switch, DGV0014A (TVSOP-14); Alternate Manufacturer: Texas Instruments; SizeArea_mm2: 23.04; SizeX_mm: 6.4; SizeAreaWB_mm2: 47.04; CompType: IC; SizeZ_mm: 1.2; AEC Category: Q200; Rating: Catalog; SizeY_mm: 3.6; AEC Qualified: N

## Sheet 19_Clock_Gen.SchDoc
size 431 x 279 mm; Date: Not shown in title block; ApprovedBy: Not shown in title block; CheckedBy: Not shown in title block; Author: Not shown in title block; CompanyName: Not shown in title block; Engineer: Not shown in title block; Organization: Not shown in title block; Address1: Not shown in title block; Address2: Not shown in title block; Address3: Not shown in title block; Address4: Not shown in title block; DocumentNumber: 11; Revision: Use project parameter SCH_Rev; SheetNumber: 11; SheetTotal: 18; PageSetup: Record=PageOptions¦CenterHorizontal=True¦CenterVertical=True¦PrintScale=1.00¦XCorrection=1.00¦YCorrection=1.00¦PrintKind=0¦BorderSize=5000000¦LeftOffset=0¦BottomOffset=0¦Orientation=2¦PaperLength=1000¦PaperWidth=1000¦Scale=100¦PaperSource=15¦PrintQuality=600¦MediaType=1¦DitherType=10¦PaperKind=Letter¦PrintScaleMode=1
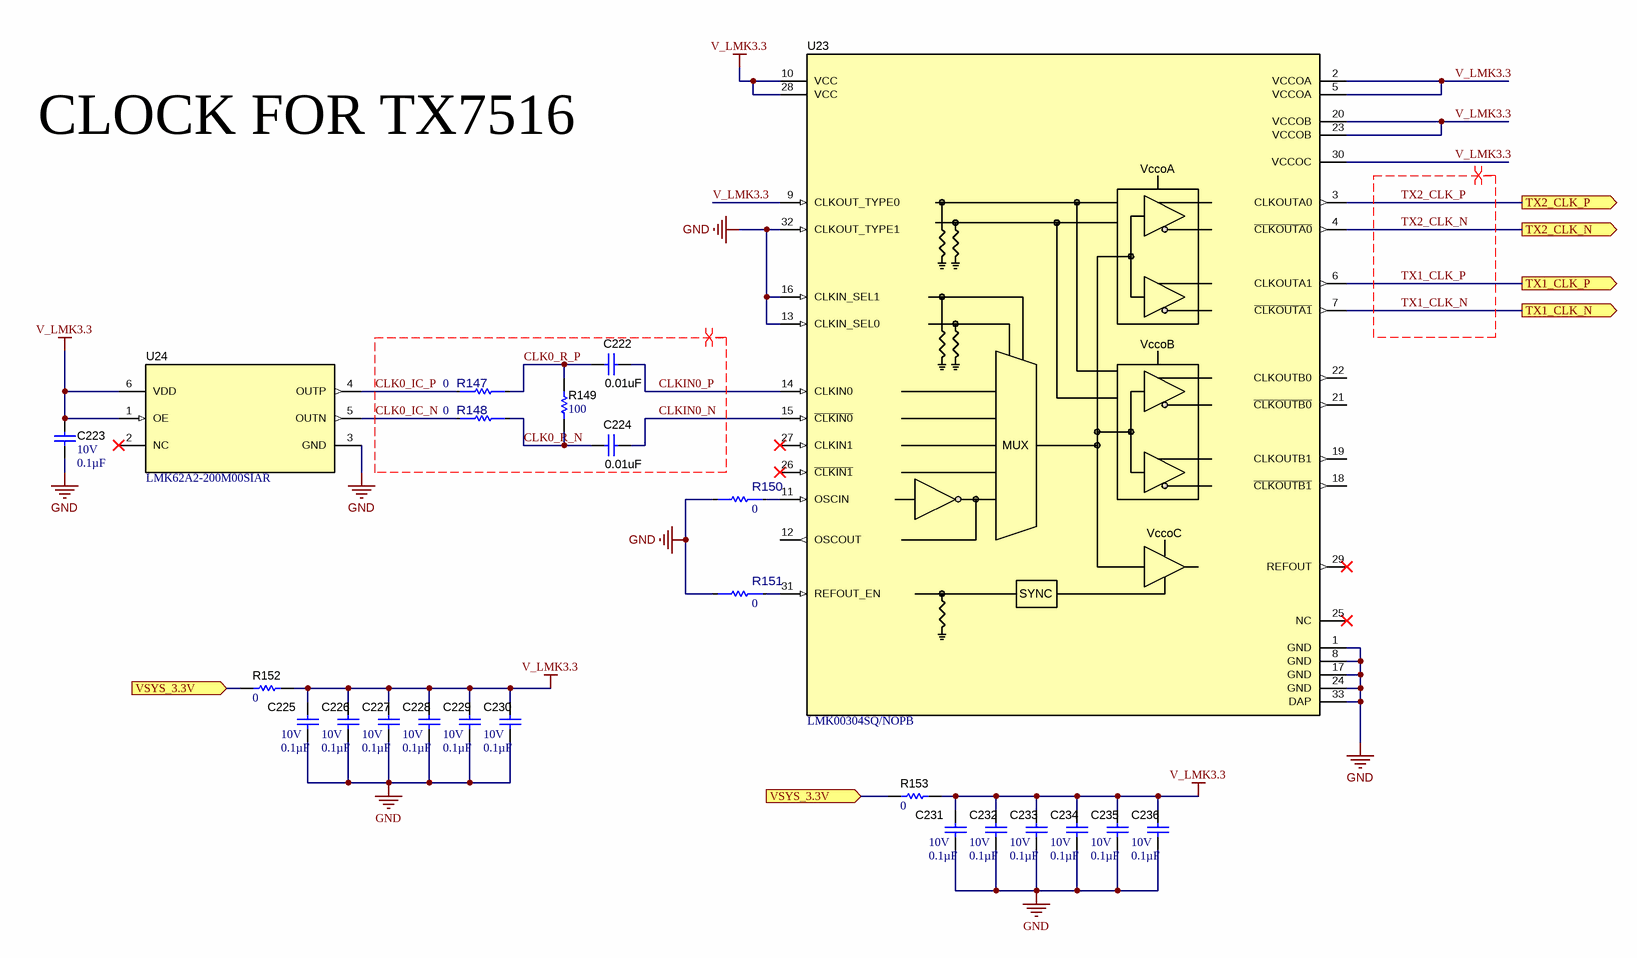
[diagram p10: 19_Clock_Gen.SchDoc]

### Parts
C222  ValueDisplayed: 0.01uF  [0402_065]  (hidden comment: 520L103KT16T)
C223  VDC_V: 10V  ValueDisplayed: 0.1µF  [0402]  (hidden comment: C0402C104K8RACTU)
C224  ValueDisplayed: 0.01uF  [0402_065]  (hidden comment: 520L103KT16T)
C225  VDC_V: 10V  ValueDisplayed: 0.1µF  [0402]  (hidden comment: C0402C104K8RACTU)
C226  VDC_V: 10V  ValueDisplayed: 0.1µF  [0402]  (hidden comment: C0402C104K8RACTU)
C227  VDC_V: 10V  ValueDisplayed: 0.1µF  [0402]  (hidden comment: C0402C104K8RACTU)
C228  VDC_V: 10V  ValueDisplayed: 0.1µF  [0402]  (hidden comment: C0402C104K8RACTU)
C229  VDC_V: 10V  ValueDisplayed: 0.1µF  [0402]  (hidden comment: C0402C104K8RACTU)
C230  VDC_V: 10V  ValueDisplayed: 0.1µF  [0402]  (hidden comment: C0402C104K8RACTU)
C231  VDC_V: 10V  ValueDisplayed: 0.1µF  [0402]  (hidden comment: C0402C104K8RACTU)
C232  VDC_V: 10V  ValueDisplayed: 0.1µF  [0402]  (hidden comment: C0402C104K8RACTU)
C233  VDC_V: 10V  ValueDisplayed: 0.1µF  [0402]  (hidden comment: C0402C104K8RACTU)
C234  VDC_V: 10V  ValueDisplayed: 0.1µF  [0402]  (hidden comment: C0402C104K8RACTU)
C235  VDC_V: 10V  ValueDisplayed: 0.1µF  [0402]  (hidden comment: C0402C104K8RACTU)
C236  VDC_V: 10V  ValueDisplayed: 0.1µF  [0402]  (hidden comment: C0402C104K8RACTU)
R147  Res_ohm: 0  [FP-ERJ-2GE0R00X_0402-MFG]  (hidden comment: ERJ-2GE0R00X)
R148  Res_ohm: 0  [FP-ERJ-2GE0R00X_0402-MFG]  (hidden comment: ERJ-2GE0R00X)
R149  ValueDisplayed: 100  [0603]  (hidden comment: CRCW0603100RFKEA)
R150  Res_ohm: 0  [FP-ERJ-2GE0R00X_0402-MFG]  (hidden comment: ERJ-2GE0R00X)
R151  Res_ohm: 0  [FP-ERJ-2GE0R00X_0402-MFG]  (hidden comment: ERJ-2GE0R00X)
R152  ValueDisplayed: 0  [0603]  (hidden comment: ERJ-L03KF10CV)
R153  ValueDisplayed: 0  [0603]  (hidden comment: ERJ-L03KF10CV)
U23  LMK00304SQ/NOPB  [RTV0032A]
U24  LMK62A2-200M00SIAR  [SIA0006B]

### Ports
TX1_CLK_N (out), TX1_CLK_P (out), TX2_CLK_N (out), TX2_CLK_P (out), VSYS_3.3V (in)

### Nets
GND: C223.2 C225.2 C226.2 C227.2 C228.2 C229.2 C230.2 C231.2 C232.2 C233.2 C234.2 C235.2 C236.2 R150.2 R151.2 U23.1(GND) U23.8(GND) U23.13(CLKIN_SEL0) U23.16(CLKIN_SEL1) U23.17(GND) U23.24(GND) U23.32(CLKOUT_TYPE1) U23.33(DAP) U24.3(GND)
V_LMK3.3: C223.1 C225.1 C226.1 C227.1 C228.1 C229.1 C230.1 C231.1 C232.1 C233.1 C234.1 C235.1 C236.1 R152.2 R153.2 U23.2(VCCOA) U23.5(VCCOA) U23.9(CLKOUT_TYPE0) U23.10(VCC) U23.20(VCCOB) U23.23(VCCOB) U23.28(VCC) U23.30(VCCOC) U24.1(OE) U24.6(VDD)
CLK0_IC_N: R148.1 U24.5(OUTN)
CLK0_IC_P: R147.1 U24.4(OUTP)
CLK0_R_N: C224.2 R148.2 R149.1
CLK0_R_P: C222.2 R147.2 R149.2
CLKIN0_N: C224.1 U23.15(~{CLKIN0})
CLKIN0_P: C222.1 U23.14(CLKIN0)
TX1_CLK_N: U23.7(~{CLKOUTA1}) ; port TX1_CLK_N
TX1_CLK_P: U23.6(CLKOUTA1) ; port TX1_CLK_P
TX2_CLK_N: U23.4(~{CLKOUTA0}) ; port TX2_CLK_N
TX2_CLK_P: U23.3(CLKOUTA0) ; port TX2_CLK_P
VSYS_3.3V: R152.1 R153.1 ; port VSYS_3.3V
NetR150_1: R150.1 U23.11(OSCIN)
NetR151_1: R151.1 U23.31(REFOUT_EN)

Not connected (* = marked no-connect by the designer): U23 12(OSCOUT) 18(~{CLKOUTB1}) 19(CLKOUTB1) 21(~{CLKOUTB0}) 22(CLKOUTB0) 25(NC)* 26(~{CLKIN1})* 27(CLKIN1)* 29(REFOUT)*; U24 2(NC)*

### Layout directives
differential pair; differential pair class 100ohm: CLK0_IC_N, CLK0_IC_P, CLK0_R_N, CLK0_R_P, CLKIN0_N, CLKIN0_P, TX1_CLK_N, TX1_CLK_P, TX2_CLK_N, TX2_CLK_P

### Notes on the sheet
- CLOCK FOR TX7516

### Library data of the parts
C222 C224 = CMP-0006210-2: CAP, CERM, 0.01 uF, 16 V, +/- 10%, X7R, 0402; Manufacturer: AT Ceramics; TaMin_C: -55°C; Polarized: N; SizeAreaWB_mm2: 3; Value1: Unknown; U/M: EA; Value: 0.01uF; TaMax_C: 125°C; SizeZ_mm: 0.65; SizeX_mm: 1; SizeY_mm: 0.5; Cap_Case: 0402; Value2: 16V; CompType: Capacitor; Cap_F: 10nF; AEC Category: Q200
C223 C225-C236 = CMP-0078241-1: CAP, CERM, 0.1 µF, 10 V,+/- 10%, X7R, 0402; Manufacturer: Kemet; TaMin_C: -55°C; Polarized: N; SizeAreaWB_mm2: 3; U/M: EA; Value: 0.1uF; TaMax_C: 125°C; SizeZ_mm: 0.6; SizeX_mm: 1; SizeY_mm: 0.5; Cap_F: 100nF; AEC Category: Q200
R147 R148 R150 R151 = CMP-0002710-1: 0 Ohms Jumper Chip Resistor 0402 (1005 Metric) Automotive AEC-Q200 Thick Film; Manufacturer: Panasonic; SizeZ_mm: 0.4mm; AEC Qualified: Yes; AEC Grade: Grade 0; Power: 100mW; Value: 0
R149 = CMP-0021991-4: RES, 100, 1%, 0.1 W, AEC-Q200 Grade 0, 0603; Manufacturer: Vishay-Dale; Power_W: 100mW; TempCo: 100 ppm/C; Value_Code: 100R; Value: 100; EIA_Code: E96; SizeX_mm: 1.6; SizeY_mm: 0.8; SizeZ_mm: 1; Value2: 0.1W; SizeArea_mm2: 1.28; AEC Qualified: Y; VDC_V: 75V; AEC Category: Q200; AEC Grade: 0
R152 R153 = CMP-0022725-3: RES, 0, 1%, 0.1 W, AEC-Q200 Grade 1, 0603; Manufacturer: Panasonic; Power_W: 100mW; TempCo: 200 ppm/C; Value_Code: R100; Value: 0.1; EIA_Code: E96; SizeX_mm: 1.6; SizeY_mm: 0.8; SizeZ_mm: 1; Value2: 0.1W; SizeArea_mm2: 1.28; AEC Qualified: Y; AEC Category: Q200; SizeAreaWB_mm2: 4.68
U23 = CMP-0065665-2: 3.1-GHz Differential Clock Buffer/Level Translator, RTV0032A (WQFN-32); Alternate Manufacturer: Texas Instruments; SizeAreaWB_mm2: 49.0; SizeArea_mm2: 25.0; SizeX_mm: 5.0; Green_REACh: Passed; SizeZ_mm: 0.8; AEC Category: Q200; Green_Lifecycle: Active; CompType: IC; AEC Qualified: N
U24 = CMP-0084525-1: High-Performance Low Jitter Standard Oscillator - 200M, SIA0006B (QFM-6); Alternate PartNumber: LMK62A2-200M00SIAT; Manufacturer: Texas Instruments; CompType: IC; SizeArea_mm2: 16; Rating: Catalog; SizeZ_mm: 1.1; SizeY_mm: 5; SizeX_mm: 3.2; SizeAreaWB_mm2: 36.4; AEC Category: Q200; AEC Qualified: N

## Sheet 20_TX7516_PartAPinout.SchDoc
size 431 x 279 mm; Date: Not shown in title block; ApprovedBy: Not shown in title block; CheckedBy: Not shown in title block; Author: Not shown in title block; CompanyName: Not shown in title block; Engineer: Not shown in title block; Organization: Not shown in title block; Address1: Not shown in title block; Address2: Not shown in title block; Address3: Not shown in title block; Address4: Not shown in title block; DocumentNumber: 12; Revision: Use project parameter SCH_Rev; SheetNumber: 12; SheetTotal: 18; PageSetup: Record=PageOptions¦CenterHorizontal=True¦CenterVertical=True¦PrintScale=1.00¦XCorrection=1.00¦YCorrection=1.00¦PrintKind=0¦BorderSize=5000000¦LeftOffset=0¦BottomOffset=0¦Orientation=2¦PaperLength=1000¦PaperWidth=1000¦Scale=100¦PaperSource=15¦PrintQuality=600¦MediaType=1¦DitherType=10¦PaperKind=Letter¦PrintScaleMode=1
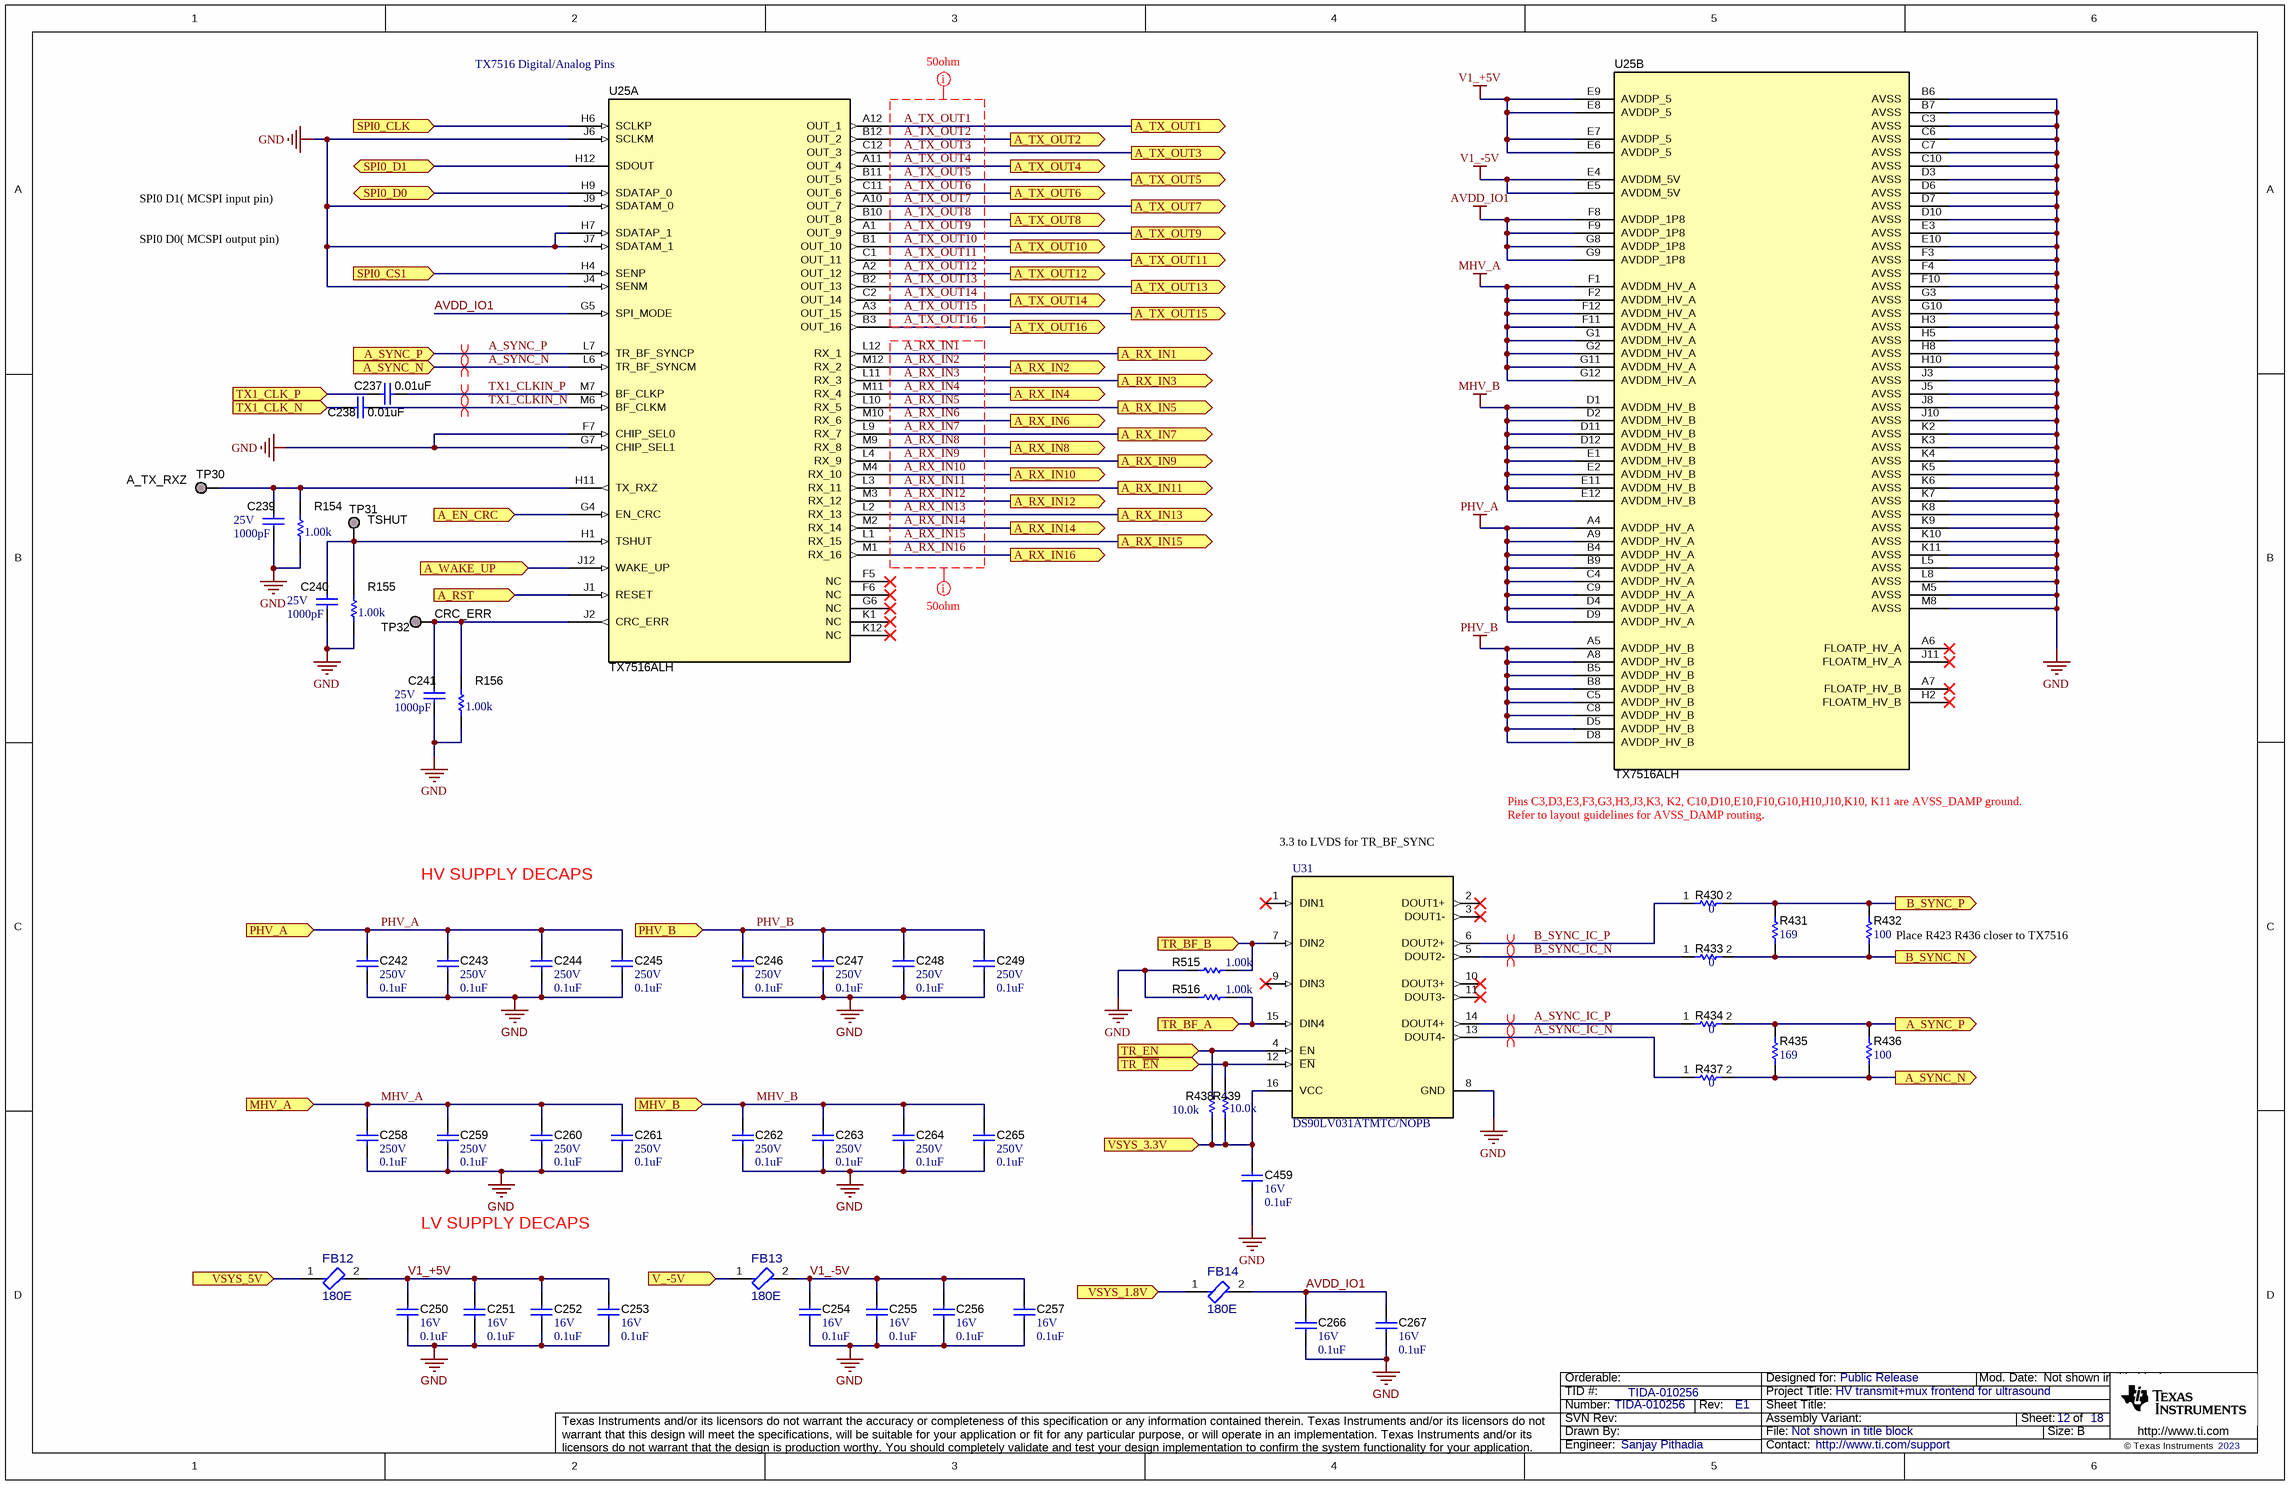
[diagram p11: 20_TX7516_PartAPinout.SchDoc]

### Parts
C237  ValueDisplayed: 0.01uF  [0402_065]  (hidden comment: 520L103KT16T)
C238  ValueDisplayed: 0.01uF  [0402_065]  (hidden comment: 520L103KT16T)
C239  VDC_V: 25V  ValueDisplayed: 1000pF  [0603]  (hidden comment: C0603C102K3GACTU)
C240  VDC_V: 25V  ValueDisplayed: 1000pF  [0603]  (hidden comment: C0603C102K3GACTU)
C241  VDC_V: 25V  ValueDisplayed: 1000pF  [0603]  (hidden comment: C0603C102K3GACTU)
C242  VDC_V: 250V  ValueDisplayed: 0.1uF  [0805_HV]  (hidden comment: C2012X7T2E104K125AA)
C243  VDC_V: 250V  ValueDisplayed: 0.1uF  [0805_HV]  (hidden comment: C2012X7T2E104K125AA)
C244  VDC_V: 250V  ValueDisplayed: 0.1uF  [0805_HV]  (hidden comment: C2012X7T2E104K125AA)
C245  VDC_V: 250V  ValueDisplayed: 0.1uF  [0805_HV]  (hidden comment: C2012X7T2E104K125AA)
C246  VDC_V: 250V  ValueDisplayed: 0.1uF  [0805_HV]  (hidden comment: C2012X7T2E104K125AA)
C247  VDC_V: 250V  ValueDisplayed: 0.1uF  [0805_HV]  (hidden comment: C2012X7T2E104K125AA)
C248  VDC_V: 250V  ValueDisplayed: 0.1uF  [0805_HV]  (hidden comment: C2012X7T2E104K125AA)
C249  VDC_V: 250V  ValueDisplayed: 0.1uF  [0805_HV]  (hidden comment: C2012X7T2E104K125AA)
C250  VDC_V: 16V  ValueDisplayed: 0.1uF  [0201_033]  (hidden comment: C0603X6S1C104K030BC)
C251  VDC_V: 16V  ValueDisplayed: 0.1uF  [0201_033]  (hidden comment: C0603X6S1C104K030BC)
C252  VDC_V: 16V  ValueDisplayed: 0.1uF  [0201_033]  (hidden comment: C0603X6S1C104K030BC)
C253  VDC_V: 16V  ValueDisplayed: 0.1uF  [0201_033]  (hidden comment: C0603X6S1C104K030BC)
C254  VDC_V: 16V  ValueDisplayed: 0.1uF  [0201_033]  (hidden comment: C0603X6S1C104K030BC)
C255  VDC_V: 16V  ValueDisplayed: 0.1uF  [0201_033]  (hidden comment: C0603X6S1C104K030BC)
C256  VDC_V: 16V  ValueDisplayed: 0.1uF  [0201_033]  (hidden comment: C0603X6S1C104K030BC)
C257  VDC_V: 16V  ValueDisplayed: 0.1uF  [0201_033]  (hidden comment: C0603X6S1C104K030BC)
C258  VDC_V: 250V  ValueDisplayed: 0.1uF  [0805_HV]  (hidden comment: C2012X7T2E104K125AA)
C259  VDC_V: 250V  ValueDisplayed: 0.1uF  [0805_HV]  (hidden comment: C2012X7T2E104K125AA)
C260  VDC_V: 250V  ValueDisplayed: 0.1uF  [0805_HV]  (hidden comment: C2012X7T2E104K125AA)
C261  VDC_V: 250V  ValueDisplayed: 0.1uF  [0805_HV]  (hidden comment: C2012X7T2E104K125AA)
C262  VDC_V: 250V  ValueDisplayed: 0.1uF  [0805_HV]  (hidden comment: C2012X7T2E104K125AA)
C263  VDC_V: 250V  ValueDisplayed: 0.1uF  [0805_HV]  (hidden comment: C2012X7T2E104K125AA)
C264  VDC_V: 250V  ValueDisplayed: 0.1uF  [0805_HV]  (hidden comment: C2012X7T2E104K125AA)
C265  VDC_V: 250V  ValueDisplayed: 0.1uF  [0805_HV]  (hidden comment: C2012X7T2E104K125AA)
C266  VDC_V: 16V  ValueDisplayed: 0.1uF  [0201_033]  (hidden comment: C0603X6S1C104K030BC)
C267  VDC_V: 16V  ValueDisplayed: 0.1uF  [0201_033]  (hidden comment: C0603X6S1C104K030BC)
C459  VDC_V: 16V  ValueDisplayed: 0.1uF  [0201_033]  (hidden comment: GRM033R61C104KE84D)
FB12  180E  [FP-MPZ1608S181ATAH0_0603-MFG]
FB13  180E  [FP-MPZ1608S181ATAH0_0603-MFG]
FB14  180E  [FP-MPZ1608S181ATAH0_0603-MFG]
R154  ValueDisplayed: 1.00k  [0603]  (hidden comment: RC0603FR-071KL)
R155  ValueDisplayed: 1.00k  [0603]  (hidden comment: RC0603FR-071KL)
R156  ValueDisplayed: 1.00k  [0603]  (hidden comment: RC0603FR-071KL)
R430  ValueDisplayed: 0  [0402]  (hidden comment: CRCW04020000Z0ED)
R431  ValueDisplayed: 169  [0402]  (hidden comment: CRCW0402169RFKED)
R432  ValueDisplayed: 100  [0402]  (hidden comment: CRCW0402100RFKED)
R433  ValueDisplayed: 0  [0402]  (hidden comment: CRCW04020000Z0ED)
R434  ValueDisplayed: 0  [0402]  (hidden comment: CRCW04020000Z0ED)
R435  ValueDisplayed: 169  [0402]  (hidden comment: CRCW0402169RFKED)
R436  ValueDisplayed: 100  [0402]  (hidden comment: CRCW0402100RFKED)
R437  ValueDisplayed: 0  [0402]  (hidden comment: CRCW04020000Z0ED)
R438  ValueDisplayed: 10.0k  [0603]  (hidden comment: RMCF0603FT10K0)
R439  ValueDisplayed: 10.0k  [0603]  (hidden comment: RMCF0603FT10K0)
R515  ValueDisplayed: 1.00k  [0603]  (hidden comment: RC0603FR-071KL)
R516  ValueDisplayed: 1.00k  [0603]  (hidden comment: RC0603FR-071KL)
TP30  A_TX_RXZ  [TP_SM_1MM]  (no BOM)
TP31  TSHUT  [TP_SM_1MM]  (no BOM)
TP32  CRC_ERR  [TP_SM_1MM]  (no BOM)
U25  TX7516ALH  [ALH0144A]  (parts A,B of 2)
U31  DS90LV031ATMTC/NOPB  [PW0016A_N]

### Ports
A_EN_CRC (in), A_RST (in), A_RX_IN1 (out), A_RX_IN2 (out), A_RX_IN3 (out), A_RX_IN4 (out), A_RX_IN5 (out), A_RX_IN6 (out), A_RX_IN7 (out), A_RX_IN8 (out), A_RX_IN9 (out), A_RX_IN10 (out), A_RX_IN11 (out), A_RX_IN12 (out), A_RX_IN13 (out), A_RX_IN14 (out), A_RX_IN15 (out), A_RX_IN16 (out), A_SYNC_N (in), A_SYNC_N (out), A_SYNC_P (in), A_SYNC_P (out), A_TX_OUT1 (out), A_TX_OUT2 (out), A_TX_OUT3 (out), A_TX_OUT4 (out), A_TX_OUT5 (out), A_TX_OUT6 (out), A_TX_OUT7 (out), A_TX_OUT8 (out), A_TX_OUT9 (out), A_TX_OUT10 (out), A_TX_OUT11 (out), A_TX_OUT12 (out), A_TX_OUT13 (out), A_TX_OUT14 (out), A_TX_OUT15 (out), A_TX_OUT16 (out), A_WAKE_UP (in), B_SYNC_N (out), B_SYNC_P (out), MHV_A (in), MHV_B (in), PHV_A (in), PHV_B (in), SPI0_CLK (in), SPI0_CS1 (in), SPI0_D0 (bidir), SPI0_D1 (bidir), TR_BF_A (in), TR_BF_B (in), TR_EN (in), TR_~{EN} (in), TX1_CLK_N (in), TX1_CLK_P (in), V_-5V (in), VSYS_1.8V (in), VSYS_3.3V (in), VSYS_5V (in)

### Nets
AVDD_IO1: C266.1 C267.1 FB14.2 U25.F8(AVDDP_1P8) U25.F9(AVDDP_1P8) U25.G5(SPI_MODE) U25.G8(AVDDP_1P8) U25.G9(AVDDP_1P8)
GND: C239.2 C240.2 C241.2 C242.2 C243.2 C244.2 C245.2 C246.2 C247.2 C248.2 C249.2 C250.2 C251.2 C252.2 C253.2 C254.2 C255.2 C256.2 C257.2 C258.2 C259.2 C260.2 C261.2 C262.2 C263.2 C264.2 C265.2 C266.2 C267.2 C459.2 R154.1 R155.1 R156.1 R515.2 R516.2 U25.B6(AVSS) U25.B7(AVSS) U25.C3(AVSS) U25.C6(AVSS) U25.C7(AVSS) U25.C10(AVSS) U25.D3(AVSS) U25.D6(AVSS) U25.D7(AVSS) U25.D10(AVSS) U25.E3(AVSS) U25.E10(AVSS) U25.F3(AVSS) U25.F4(AVSS) U25.F7(CHIP_SEL0) U25.F10(AVSS) U25.G3(AVSS) U25.G7(CHIP_SEL1) U25.G10(AVSS) U25.H3(AVSS) U25.H5(AVSS) U25.H7(SDATAP_1) U25.H8(AVSS) U25.H10(AVSS) U25.J3(AVSS) U25.J4(SENM) U25.J5(AVSS) U25.J6(SCLKM) U25.J7(SDATAM_1) U25.J8(AVSS) U25.J9(SDATAM_0) U25.J10(AVSS) U25.K2(AVSS) U25.K3(AVSS) U25.K4(AVSS) U25.K5(AVSS) U25.K6(AVSS) U25.K7(AVSS) U25.K8(AVSS) U25.K9(AVSS) U25.K10(AVSS) U25.K11(AVSS) U25.L5(AVSS) U25.L8(AVSS) U25.M5(AVSS) U25.M8(AVSS) U31.8(GND)
MHV_A: C258.1 C259.1 C260.1 C261.1 U25.F1(AVDDM_HV_A) U25.F2(AVDDM_HV_A) U25.F11(AVDDM_HV_A) U25.F12(AVDDM_HV_A) U25.G1(AVDDM_HV_A) U25.G2(AVDDM_HV_A) U25.G11(AVDDM_HV_A) U25.G12(AVDDM_HV_A) ; port MHV_A
MHV_B: C262.1 C263.1 C264.1 C265.1 U25.D1(AVDDM_HV_B) U25.D2(AVDDM_HV_B) U25.D11(AVDDM_HV_B) U25.D12(AVDDM_HV_B) U25.E1(AVDDM_HV_B) U25.E2(AVDDM_HV_B) U25.E11(AVDDM_HV_B) U25.E12(AVDDM_HV_B) ; port MHV_B
PHV_A: C242.1 C243.1 C244.1 C245.1 U25.A4(AVDDP_HV_A) U25.A9(AVDDP_HV_A) U25.B4(AVDDP_HV_A) U25.B9(AVDDP_HV_A) U25.C4(AVDDP_HV_A) U25.C9(AVDDP_HV_A) U25.D4(AVDDP_HV_A) U25.D9(AVDDP_HV_A) ; port PHV_A
PHV_B: C246.1 C247.1 C248.1 C249.1 U25.A5(AVDDP_HV_B) U25.A8(AVDDP_HV_B) U25.B5(AVDDP_HV_B) U25.B8(AVDDP_HV_B) U25.C5(AVDDP_HV_B) U25.C8(AVDDP_HV_B) U25.D5(AVDDP_HV_B) U25.D8(AVDDP_HV_B) ; port PHV_B
V1_+5V: C250.1 C251.1 C252.1 C253.1 FB12.2 U25.E6(AVDDP_5) U25.E7(AVDDP_5) U25.E8(AVDDP_5) U25.E9(AVDDP_5)
V1_-5V: C254.1 C255.1 C256.1 C257.1 FB13.2 U25.E4(AVDDM_5V) U25.E5(AVDDM_5V)
A_RX_IN1: U25.L12(RX_1) ; port A_RX_IN1
A_RX_IN2: U25.M12(RX_2) ; port A_RX_IN2
A_RX_IN3: U25.L11(RX_3) ; port A_RX_IN3
A_RX_IN4: U25.M11(RX_4) ; port A_RX_IN4
A_RX_IN5: U25.L10(RX_5) ; port A_RX_IN5
A_RX_IN6: U25.M10(RX_6) ; port A_RX_IN6
A_RX_IN7: U25.L9(RX_7) ; port A_RX_IN7
A_RX_IN8: U25.M9(RX_8) ; port A_RX_IN8
A_RX_IN9: U25.L4(RX_9) ; port A_RX_IN9
A_RX_IN10: U25.M4(RX_10) ; port A_RX_IN10
A_RX_IN11: U25.L3(RX_11) ; port A_RX_IN11
A_RX_IN12: U25.M3(RX_12) ; port A_RX_IN12
A_RX_IN13: U25.L2(RX_13) ; port A_RX_IN13
A_RX_IN14: U25.M2(RX_14) ; port A_RX_IN14
A_RX_IN15: U25.L1(RX_15) ; port A_RX_IN15
A_RX_IN16: U25.M1(RX_16) ; port A_RX_IN16
A_SYNC_IC_N: R437.1 U31.13(DOUT4-)
A_SYNC_IC_P: R434.1 U31.14(DOUT4+)
A_SYNC_N: R435.1 R436.1 R437.2 U25.L6(TR_BF_SYNCM) ; port A_SYNC_N
A_SYNC_P: R434.2 R435.2 R436.2 U25.L7(TR_BF_SYNCP) ; port A_SYNC_P
A_TX_OUT1: U25.A12(OUT_1) ; port A_TX_OUT1
A_TX_OUT2: U25.B12(OUT_2) ; port A_TX_OUT2
A_TX_OUT3: U25.C12(OUT_3) ; port A_TX_OUT3
A_TX_OUT4: U25.A11(OUT_4) ; port A_TX_OUT4
A_TX_OUT5: U25.B11(OUT_5) ; port A_TX_OUT5
A_TX_OUT6: U25.C11(OUT_6) ; port A_TX_OUT6
A_TX_OUT7: U25.A10(OUT_7) ; port A_TX_OUT7
A_TX_OUT8: U25.B10(OUT_8) ; port A_TX_OUT8
A_TX_OUT9: U25.A1(OUT_9) ; port A_TX_OUT9
A_TX_OUT10: U25.B1(OUT_10) ; port A_TX_OUT10
A_TX_OUT11: U25.C1(OUT_11) ; port A_TX_OUT11
A_TX_OUT12: U25.A2(OUT_12) ; port A_TX_OUT12
A_TX_OUT13: U25.B2(OUT_13) ; port A_TX_OUT13
A_TX_OUT14: U25.C2(OUT_14) ; port A_TX_OUT14
A_TX_OUT15: U25.A3(OUT_15) ; port A_TX_OUT15
A_TX_OUT16: U25.B3(OUT_16) ; port A_TX_OUT16
B_SYNC_IC_N: R433.1 U31.5(DOUT2-)
B_SYNC_IC_P: R430.1 U31.6(DOUT2+)
B_SYNC_N: R431.1 R432.1 R433.2 ; port B_SYNC_N
B_SYNC_P: R430.2 R431.2 R432.2 ; port B_SYNC_P
TX1_CLK_N: C238.2 ; port TX1_CLK_N
TX1_CLK_P: C237.2 ; port TX1_CLK_P
TX1_CLKIN_N: C238.1 U25.M6(BF_CLKM)
TX1_CLKIN_P: C237.1 U25.M7(BF_CLKP)
V_-5V: FB13.1 ; port V_-5V
VSYS_1.8V: FB14.1 ; port VSYS_1.8V
VSYS_3.3V: C459.1 R438.1 R439.1 U31.16(VCC) ; port VSYS_3.3V
VSYS_5V: FB12.1 ; port VSYS_5V
NetC239_1: C239.1 R154.2 TP30.1 U25.H11(TX_RXZ)
NetC240_1: C240.1 R155.2 TP31.1 U25.H1(TSHUT)
NetC241_1: C241.1 R156.2 TP32.1 U25.J2(CRC_ERR)
NetR428_2: R515.1 U31.7(DIN2) ; port TR_BF_B
NetR429_2: R516.1 U31.15(DIN4) ; port TR_BF_A
NetR438_2: R438.2 U31.4(EN) ; port TR_EN
NetR439_2: R439.2 U31.12(~{EN}) ; port TR_~{EN}
NetR513_2: U25.H4(SENP) ; port SPI0_CS1
NetU17_A8: U25.H9(SDATAP_0) ; port SPI0_D0
NetU17_A17: U25.J12(WAKE_UP) ; port A_WAKE_UP
NetU17_B8: U25.H6(SCLKP) ; port SPI0_CLK
NetU17_B15: U25.G4(EN_CRC) ; port A_EN_CRC
NetU17_B16: U25.J1(RESET) ; port A_RST
NetU17_C9: U25.H12(SDOUT) ; port SPI0_D1

Not connected (* = marked no-connect by the designer): U25 A6(FLOATP_HV_A)* A7(FLOATP_HV_B)* F5(NC)* F6(NC)* G6(NC)* H2(FLOATM_HV_B)* J11(FLOATM_HV_A)* K1(NC)* K12(NC)*; U31 1(DIN1)* 2(DOUT1+)* 3(DOUT1-)* 9(DIN3)* 10(DOUT3+)* 11(DOUT3-)*

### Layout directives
differential pair; differential pair class 100ohm: A_SYNC_IC_N, A_SYNC_IC_P, A_SYNC_N, A_SYNC_P, B_SYNC_IC_N, B_SYNC_IC_P, TX1_CLKIN_N, TX1_CLKIN_P
net class A_TX_OUT: A_TX_OUT1, A_TX_OUT2, A_TX_OUT3, A_TX_OUT4, A_TX_OUT5, A_TX_OUT6, A_TX_OUT7, A_TX_OUT8, A_TX_OUT9, A_TX_OUT10, A_TX_OUT11, A_TX_OUT12, A_TX_OUT13, A_TX_OUT14, A_TX_OUT15, A_TX_OUT16
net class A_RX_IN: A_RX_IN1, A_RX_IN2, A_RX_IN3, A_RX_IN4, A_RX_IN5, A_RX_IN6, A_RX_IN7, A_RX_IN8, A_RX_IN9, A_RX_IN10, A_RX_IN11, A_RX_IN12, A_RX_IN13, A_RX_IN14, A_RX_IN15, A_RX_IN16

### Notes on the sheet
- TX7516 Digital/Analog Pins
- SPI0 D1( MCSPI input pin)
- SPI0 D0( MCSPI output pin)
- Pins C3,D3,E3,F3,G3,H3,J3,K3, K2, C10,D10,E10,F10,G10,H10,J10,K10, K11 are AVSS_DAMP ground.
- Refer to layout guidelines for AVSS_DAMP routing.
- HV SUPPLY DECAPS
- 3.3 to LVDS for TR_BF_SYNC
- (near R432) Place R423 R436 closer to TX7516
- (near FB13) LV SUPPLY DECAPS

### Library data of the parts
C237 C238 = CMP-0006210-2: as C222 on sheet 19_Clock_Gen
C239-C241 = CMP-0006846-4: CAP, CERM, 1000 pF, 25 V, +/- 10%, C0G/NP0, 0603; Manufacturer: Kemet; TaMin_C: -55°C; ESR_ohm: 0; Polarized: N; SizeAreaWB_mm2: 4.68; Value1: 0 ohm; U/M: EA; Value: 1000pF; TaMax_C: 125°C; SizeZ_mm: 1; SizeX_mm: 1.6; SizeY_mm: 0.8; SizeArea_mm2: 1.28; Cap_F: 1nF; IRMS_A: 0A; AEC Category: Q200
C242-C249 C258-C265 = CMP-0007897-1: CAP, CERM, 0.1 uF, 250 V, +/- 10%, X7T, 0805; Manufacturer: TDK; TaMin_C: -55°C; Polarized: N; SizeAreaWB_mm2: 6.75; Value1: Unknown; U/M: EA; Value: 0.1uF; TaMax_C: 125°C; SizeZ_mm: 1.45; SizeX_mm: 2; SizeY_mm: 1.25; Cap_Case: 0805; SizeArea_mm2: 2.5; Cap_F: 100nF; AEC Category: Q200
C250-C257 C266 C267 = CMP-0009637-3: CAP, CERM, 0.1 uF, 16 V, +/- 10%, X6S, 0201; Manufacturer: TDK; TaMin_C: -55°C; Polarized: N; SizeAreaWB_mm2: 2.08; Value1: Unknown; U/M: EA; Value: 0.1uF; TaMax_C: 105°C; SizeZ_mm: 0.33; SizeX_mm: 0.6; SizeY_mm: 0.3; Cap_Case: 0201; SizeArea_mm2: 0.18; Cap_F: 100nF; AEC Category: Q200
C459 = CMP-0009717-2: as C137 on sheet 17_AM243x_SocPower
FB12-FB14 = CMP-0092257-1: as FB3 on sheet 17_AM243x_SocPower
R154-R156 R515 R516 = CMP-0022895-5: RES, 1.00 k, 1%, 0.1 W, 0603; Manufacturer: Yageo; Power_W: 100mW; TempCo: 100 ppm/C; Value_Code: 1k00; Value: 1.00k; EIA_Code: E96; Res_ohm: 1k; SizeX_mm: 1.6; SizeY_mm: 0.8; SizeZ_mm: 1; Value2: 0.1W; SizeArea_mm2: 1.28; AEC Qualified: N; VDC_V: 75V; AEC Category: Q200; SizeAreaWB_mm2: 4.68
R430 R433 R434 R437 = CMP-0026822-3: RES, 0, 5%, 0.063 W, AEC-Q200 Grade 0, 0402; Manufacturer: Vishay-Dale; Power_W: 63mW; TempCo: 200 ppm/C; Value_Code: 0000; Value: 0; EIA_Code: E24; SizeX_mm: 1; SizeY_mm: 0.5; SizeZ_mm: 0.6; Value2: 0.063W; AEC Qualified: Y; VDC_V: 50V; AEC Category: Q200
R431 R435 = CMP-0026039-3: RES, 169, 1%, 0.063 W, AEC-Q200 Grade 0, 0402; Manufacturer: Vishay-Dale; Power_W: 63mW; TempCo: 100 ppm/C; Value_Code: 169R; Value: 169; EIA_Code: E96; SizeX_mm: 1; SizeY_mm: 0.5; SizeZ_mm: 0.6; Value2: 0.063W; AEC Qualified: Y; VDC_V: 50V; AEC Category: Q200; AEC Grade: 0
R432 R436 = CMP-0025951-3: RES, 100, 1%, 0.063 W, AEC-Q200 Grade 0, 0402; Manufacturer: Vishay-Dale; Power_W: 63mW; TempCo: 100 ppm/C; Value_Code: 100R; Value: 100; EIA_Code: E96; SizeX_mm: 1; SizeY_mm: 0.5; SizeZ_mm: 0.6; Value2: 0.063W; AEC Qualified: Y; VDC_V: 50V; AEC Category: Q200; AEC Grade: 0
R438 R439 = CMP-0023341-3: RES, 10.0 k, 1%, 0.1 W, AEC-Q200 Grade 0, 0603; Manufacturer: Stackpole Electronics Inc; Power_W: 100mW; TempCo: 100 ppm/C; Value_Code: 10k0; U/M: EA; Value: 10.0k; EIA_Code: E96; Res_ohm: 10k; SizeX_mm: 1.6; SizeY_mm: 0.8; SizeZ_mm: 1; Value2: 0.1W; SizeArea_mm2: 1.28; AEC Qualified: Y; VDC_V: 75V; AEC Grade: 0; AEC Category: Q200
TP30-TP32 = CMP-0003825-1: 1mm Test Point, SMT; Manufacturer: Any
U25 = CMP-0860806-2: Five-Level, 16-Channel Transmitter with T/R Switch, and On-Chip Beamformer, ALH0144A (FCBGA-144); Manufacturer: Texas Instruments; SizeZ_mm: 1.321; SizeArea_mm2: 100; SizeY_mm: 10; AEC Qualified: N; AEC Category: Q200; CompType: IC; SizeAreaWB_mm2: 144
U31 = CMP-0069809-1: 3V LVDS Quad CMOS Differential Line Driver, 16-pin TSSOP; Manufacturer: Texas Instruments; PackageTopMarking: NS2ZXYTT*DS90LV*031AT; PowerWise: N; CompType: Interface IC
